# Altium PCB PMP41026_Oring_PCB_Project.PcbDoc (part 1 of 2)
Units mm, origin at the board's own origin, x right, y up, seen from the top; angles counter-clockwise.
Board outline 34.25 x 35.26 mm, 8 copper layers (Top Layer, Layer 2, Layer 3, Layer 4, Layer 5, Layer 6, Layer 7, Bottom Layer), stack 1.271 mm thick; 34 components, 15 nets, 290 pads, 1015 vias.
Unrouted connection lines stored in the file: 1.
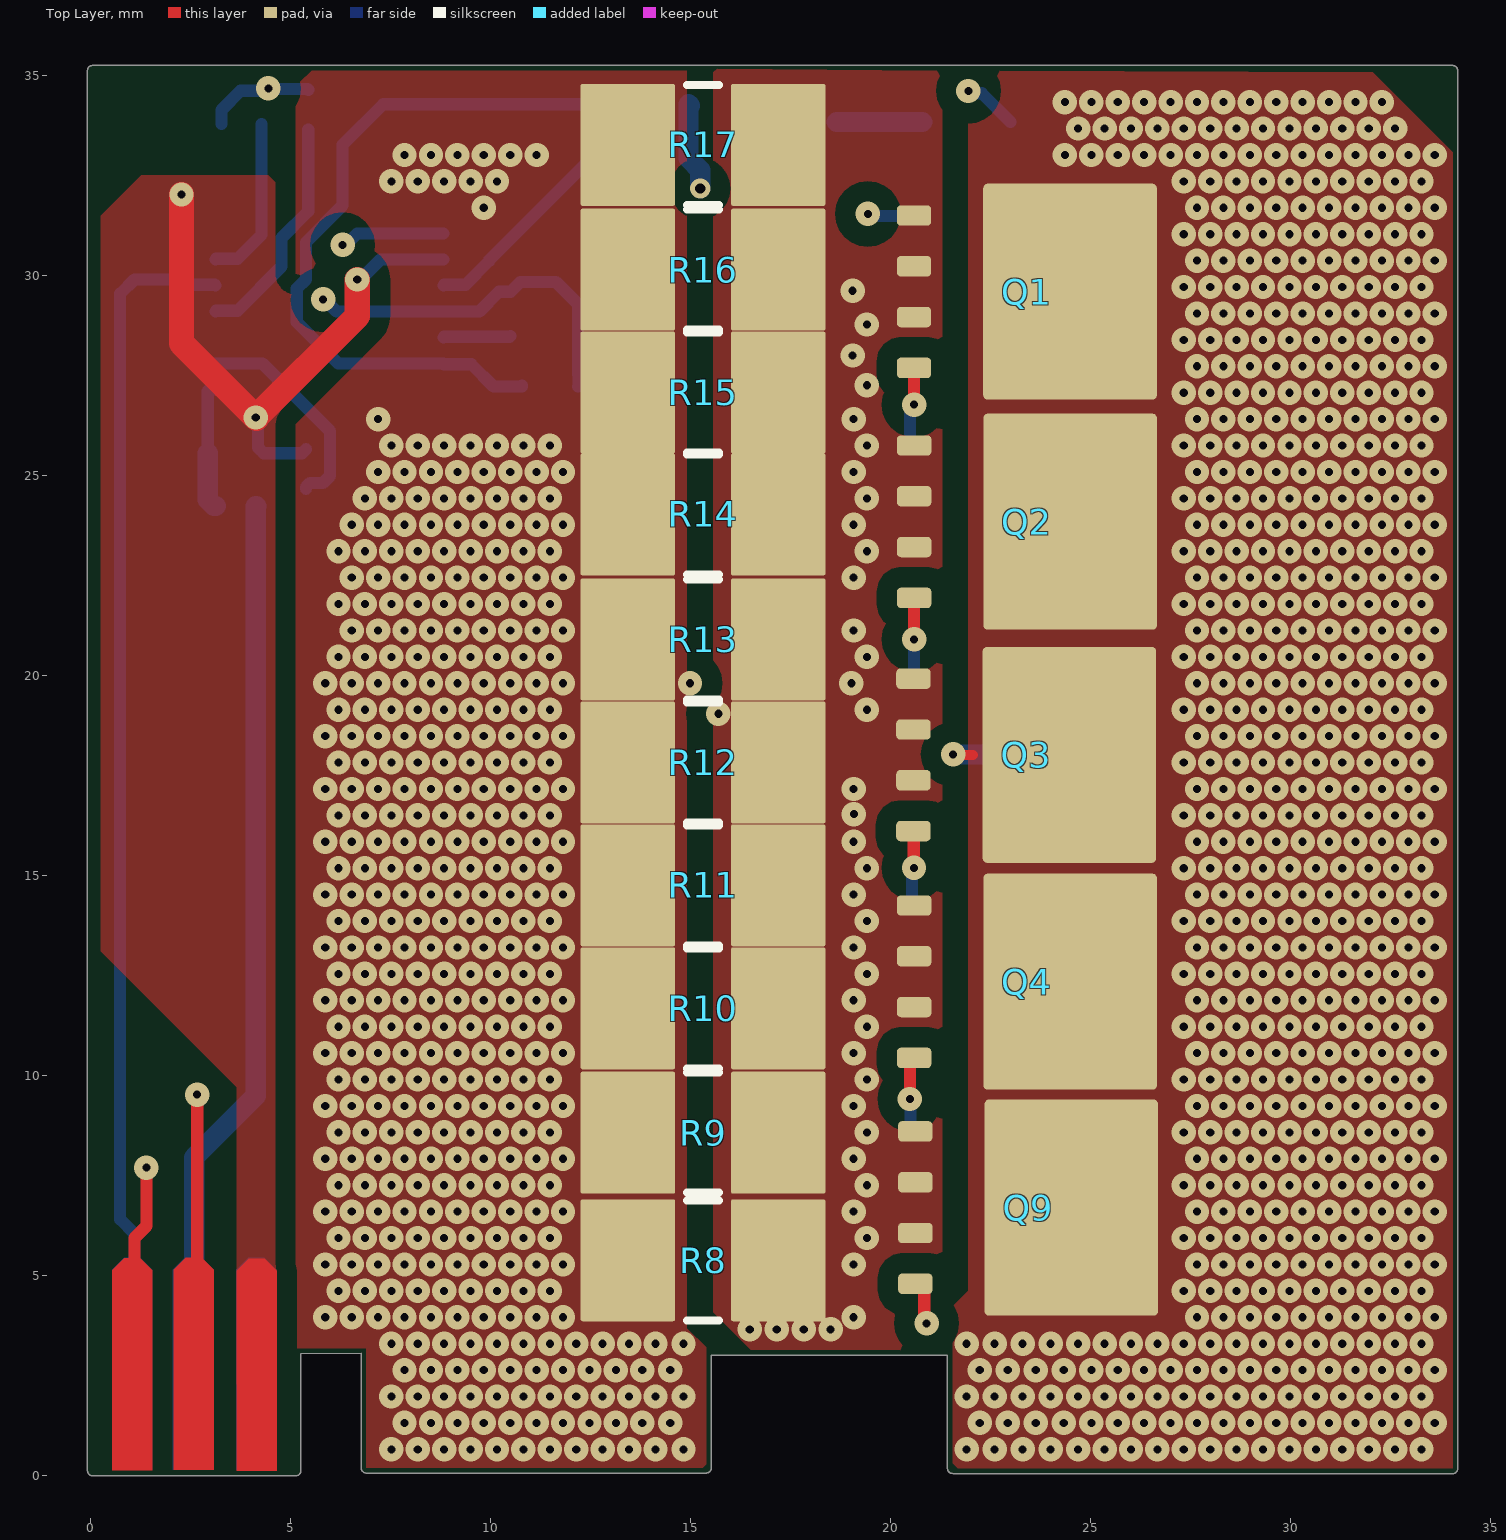
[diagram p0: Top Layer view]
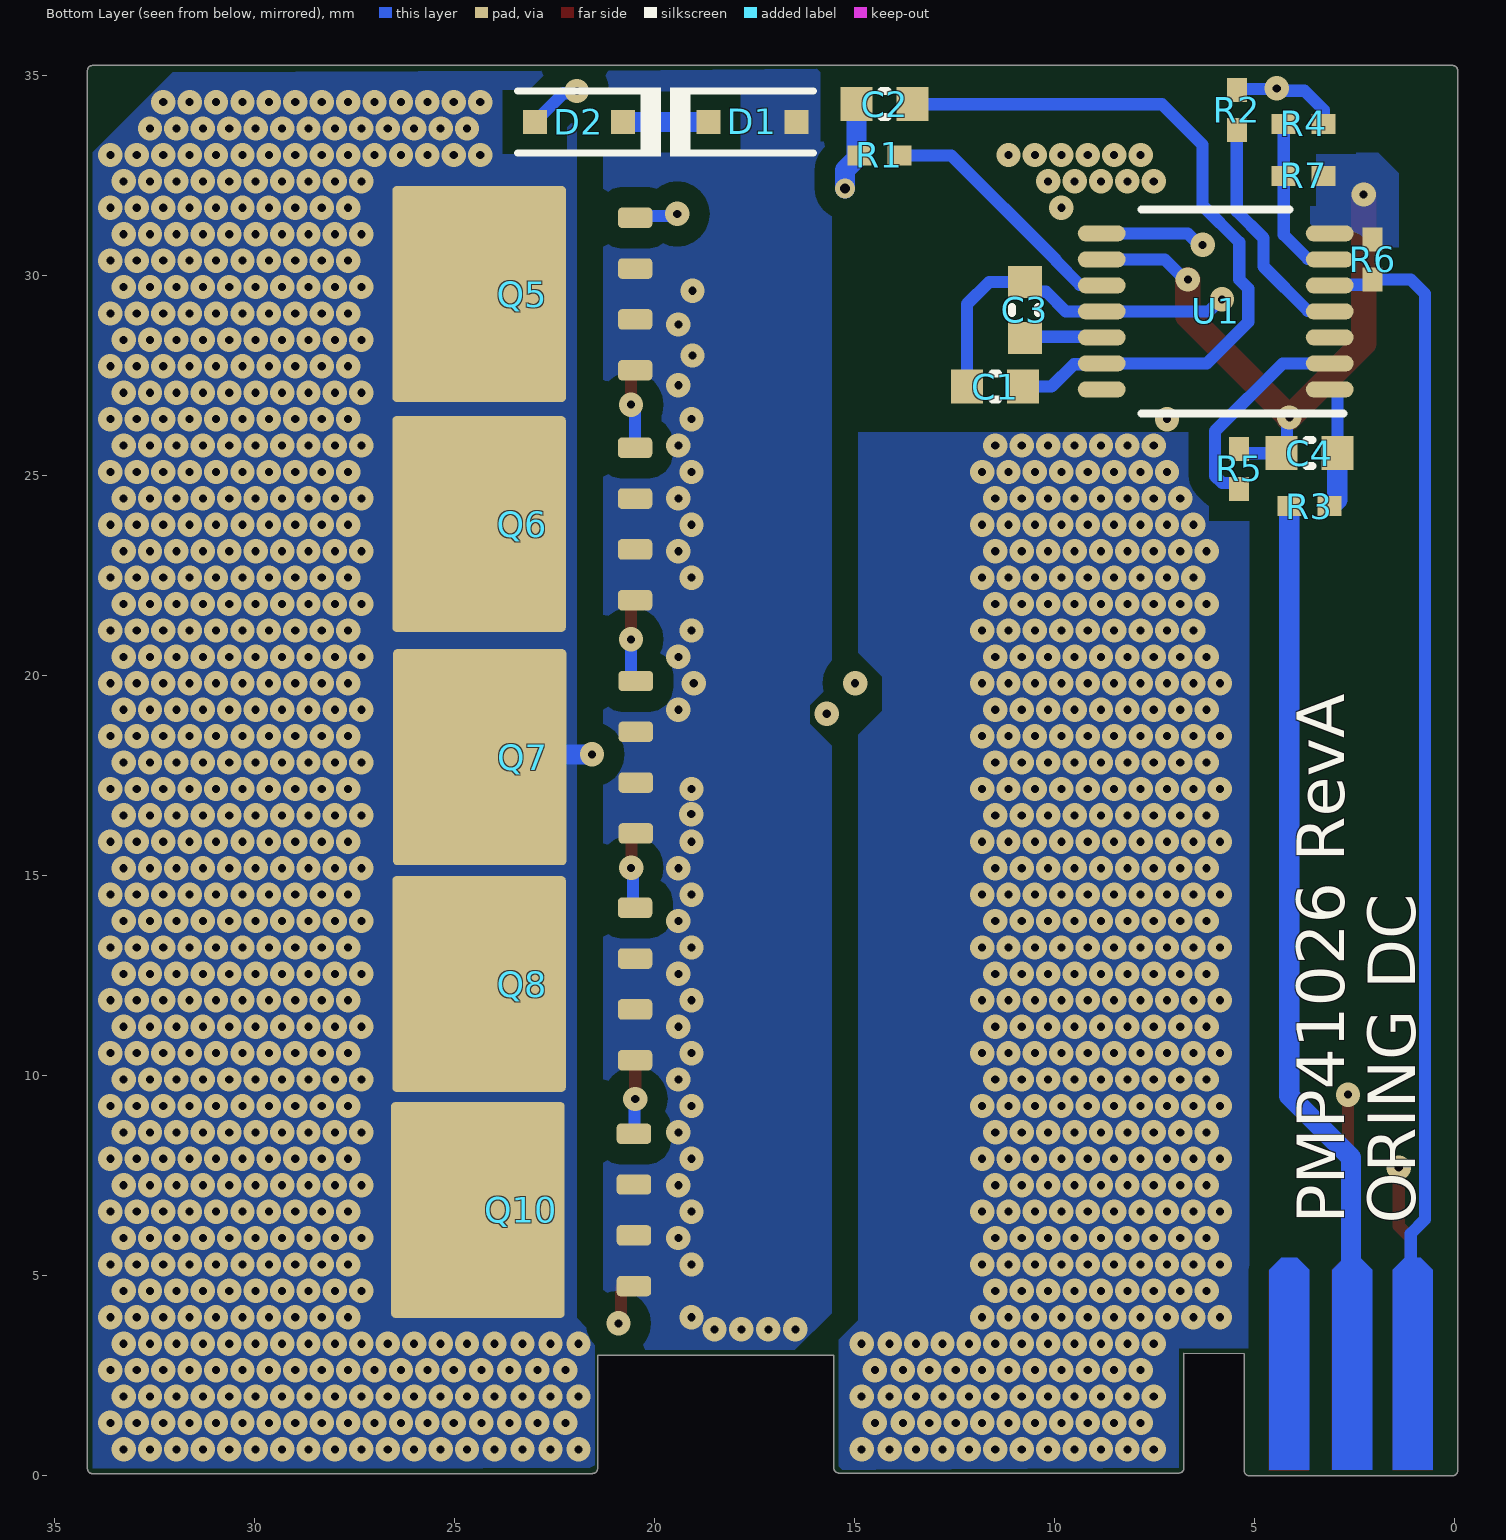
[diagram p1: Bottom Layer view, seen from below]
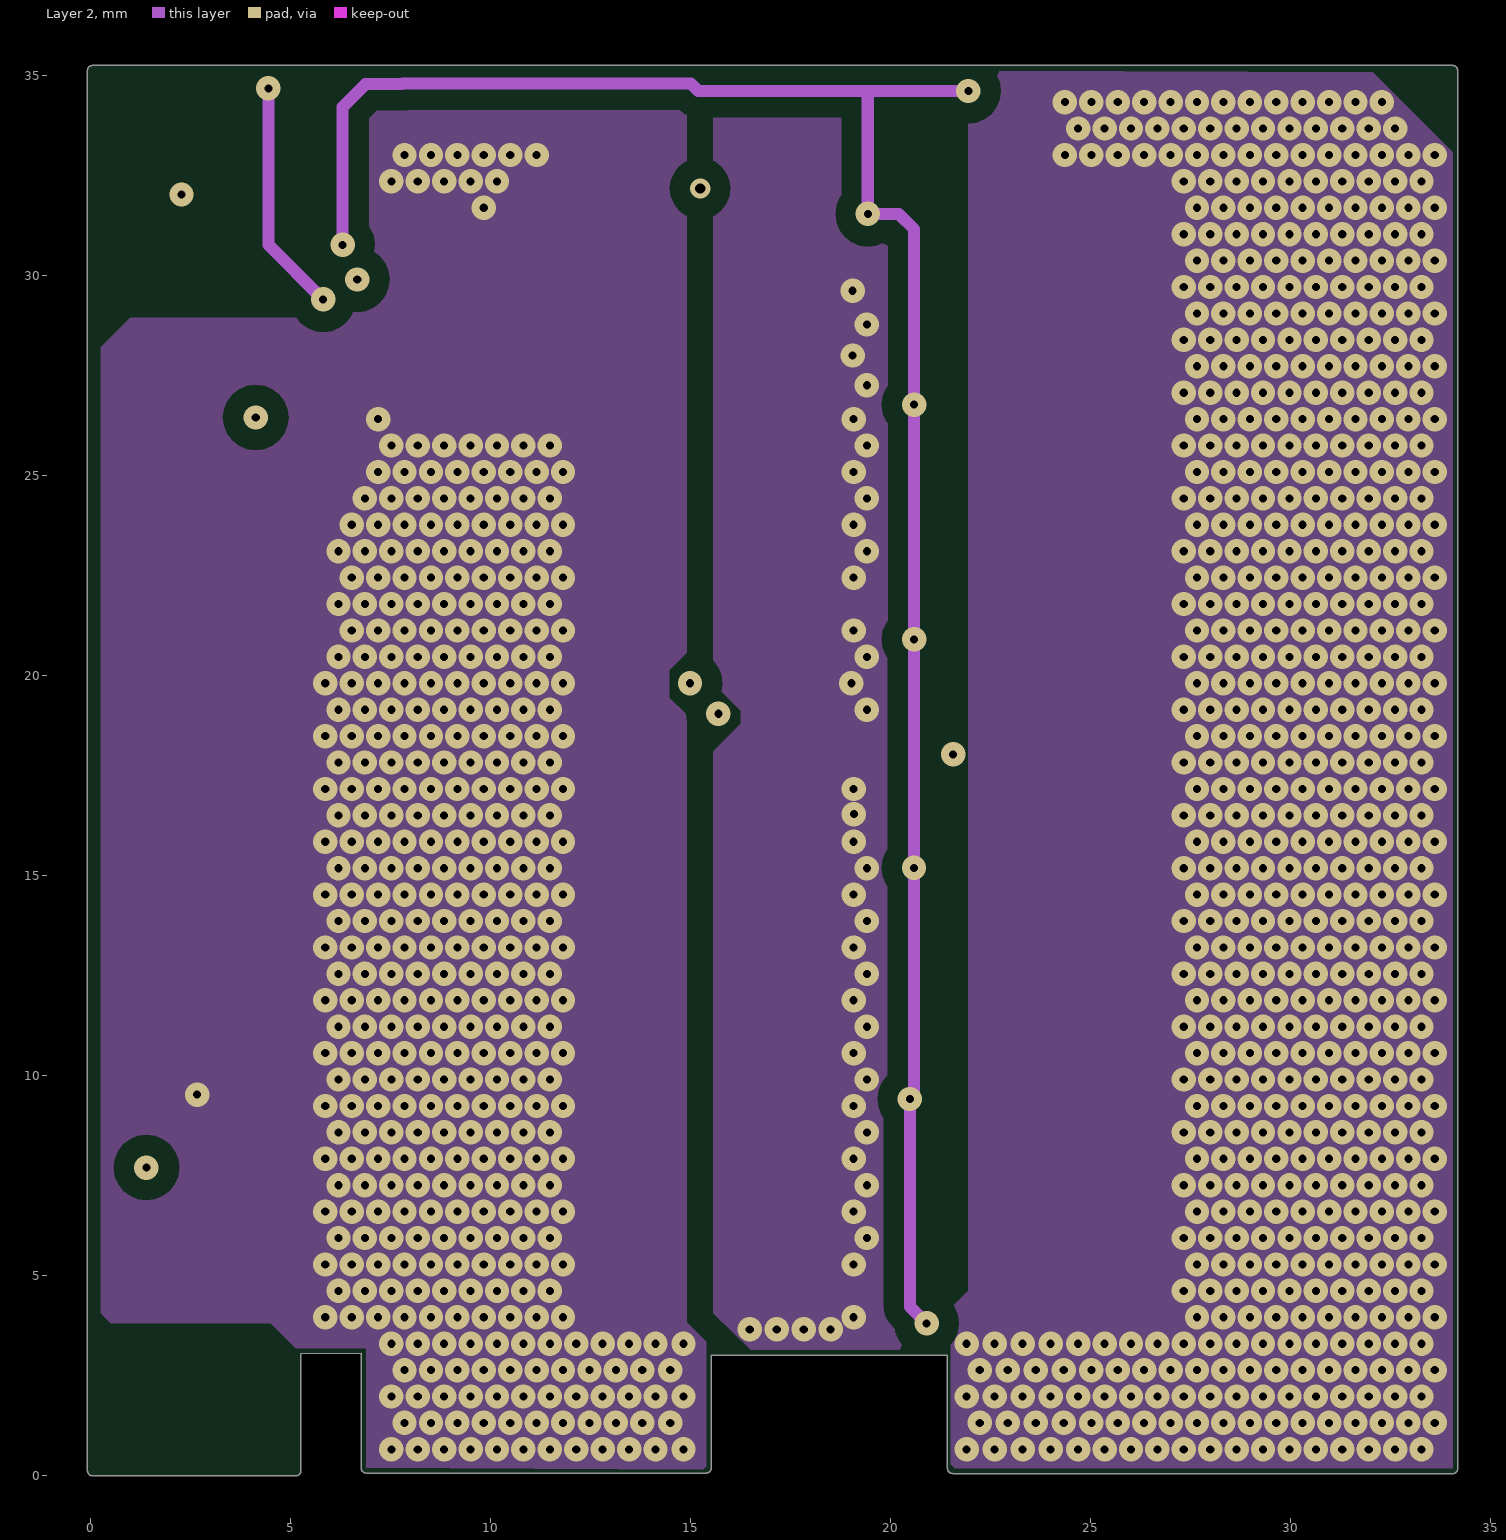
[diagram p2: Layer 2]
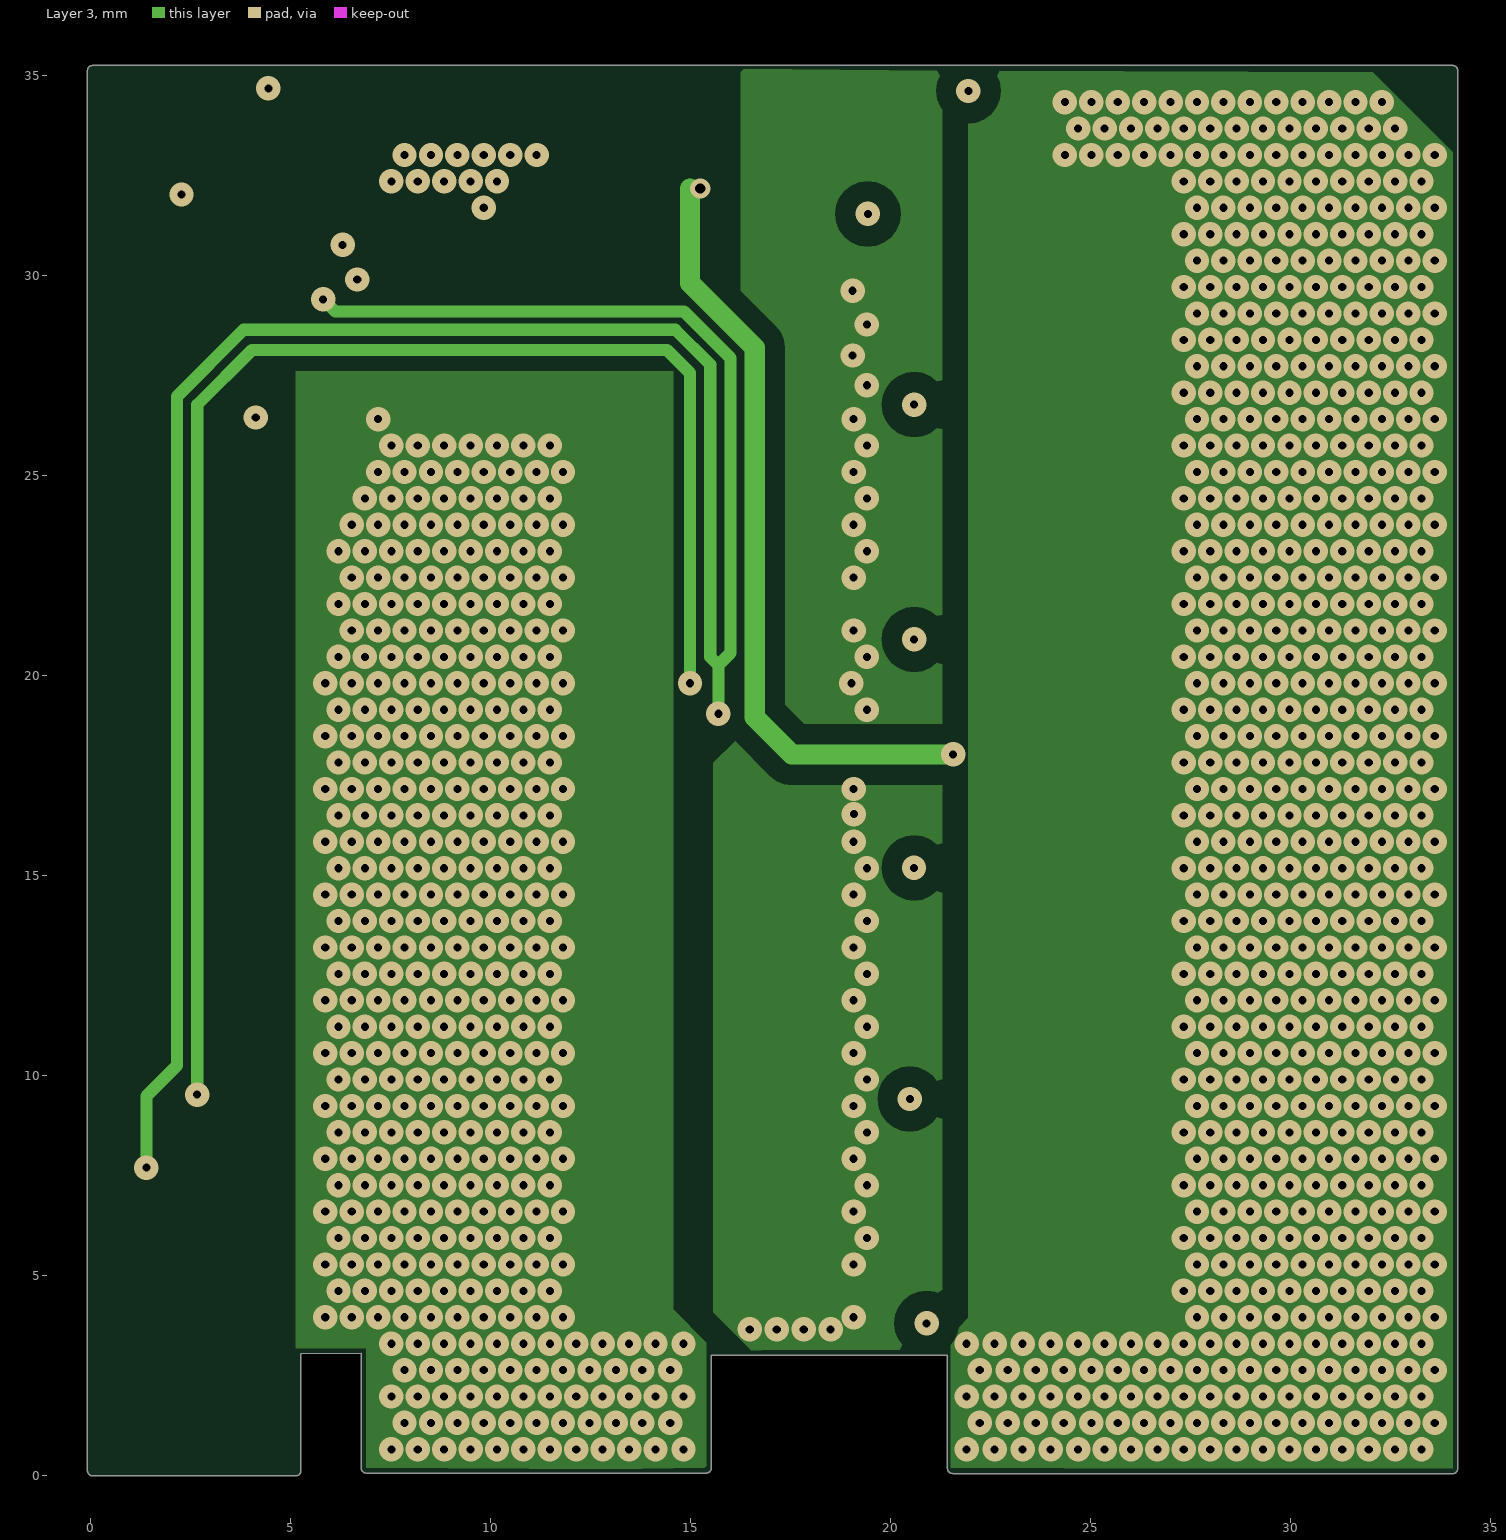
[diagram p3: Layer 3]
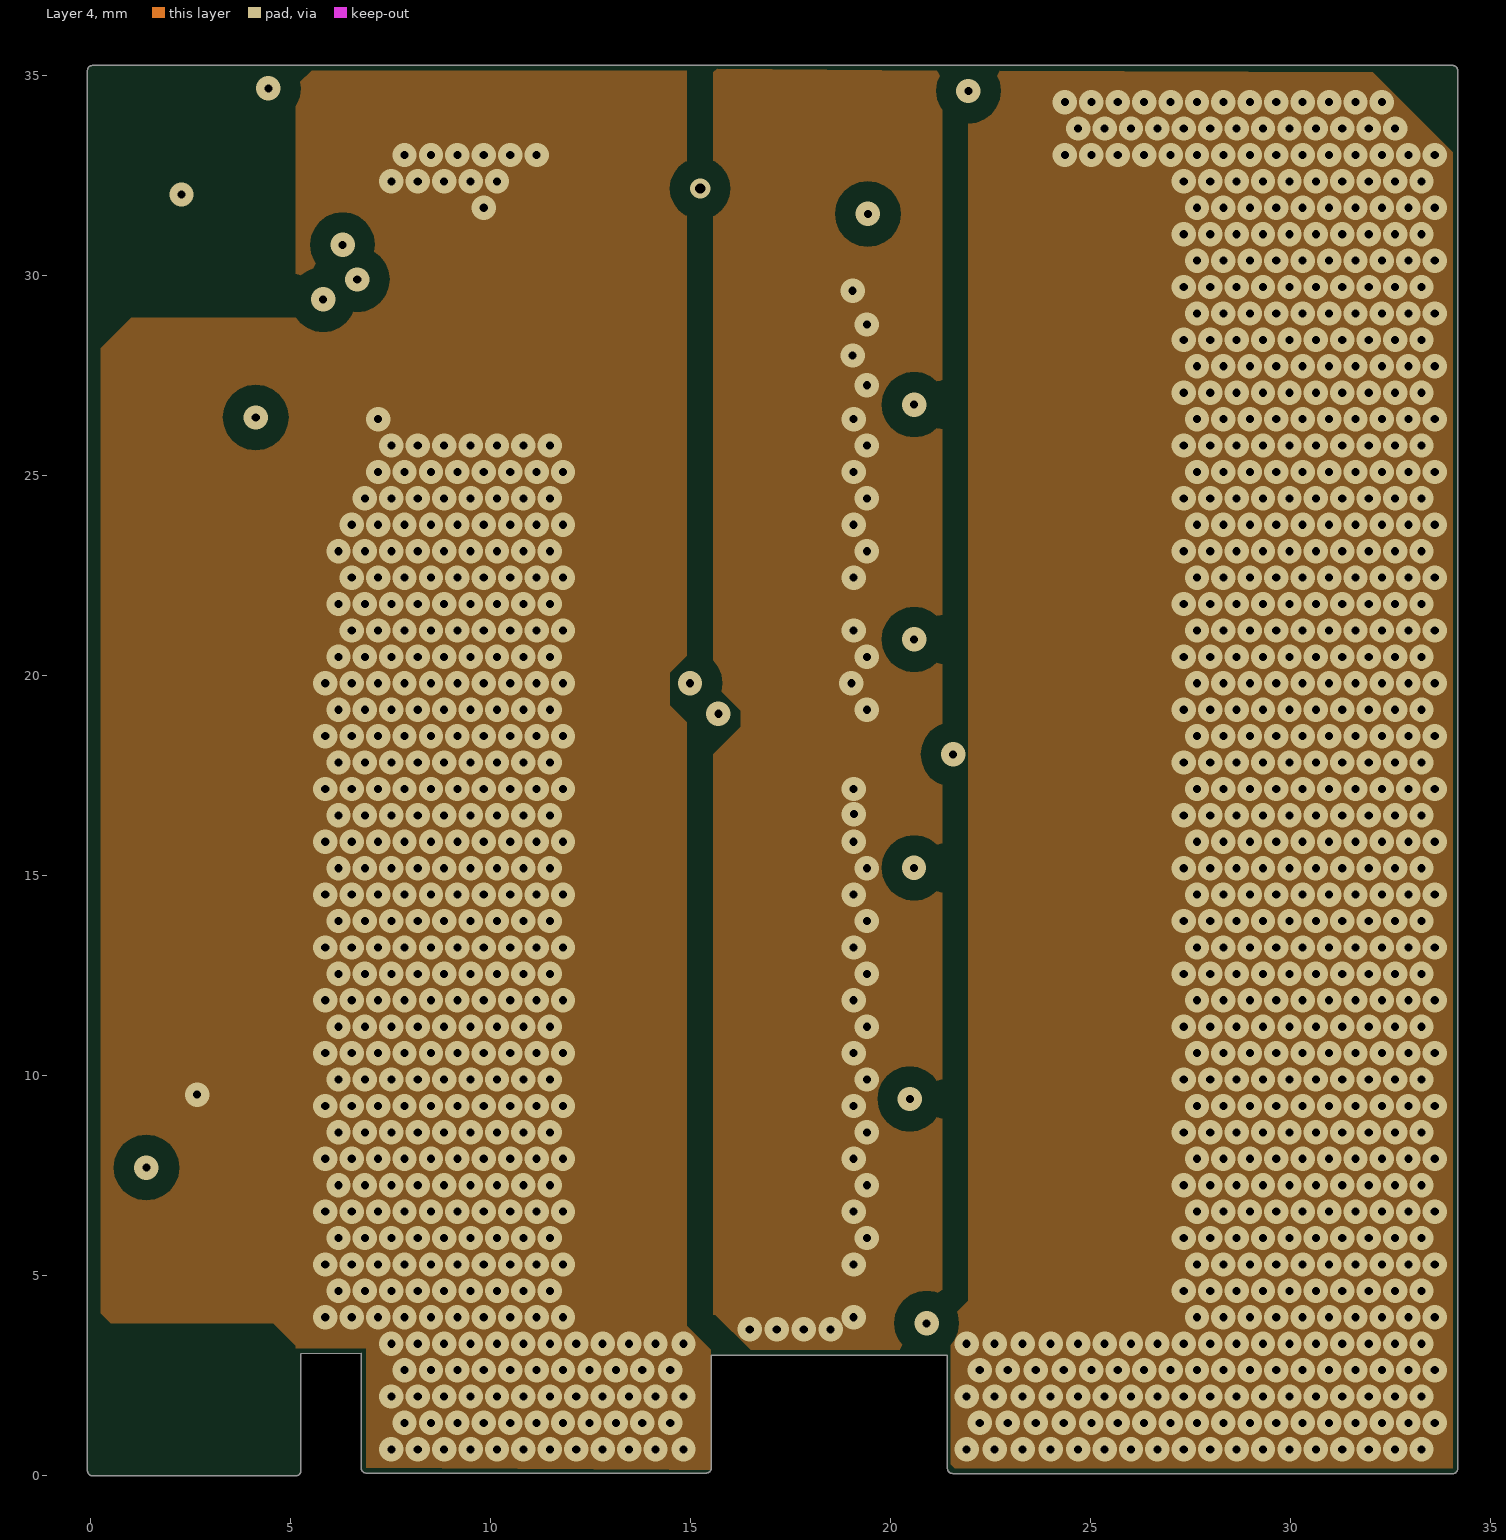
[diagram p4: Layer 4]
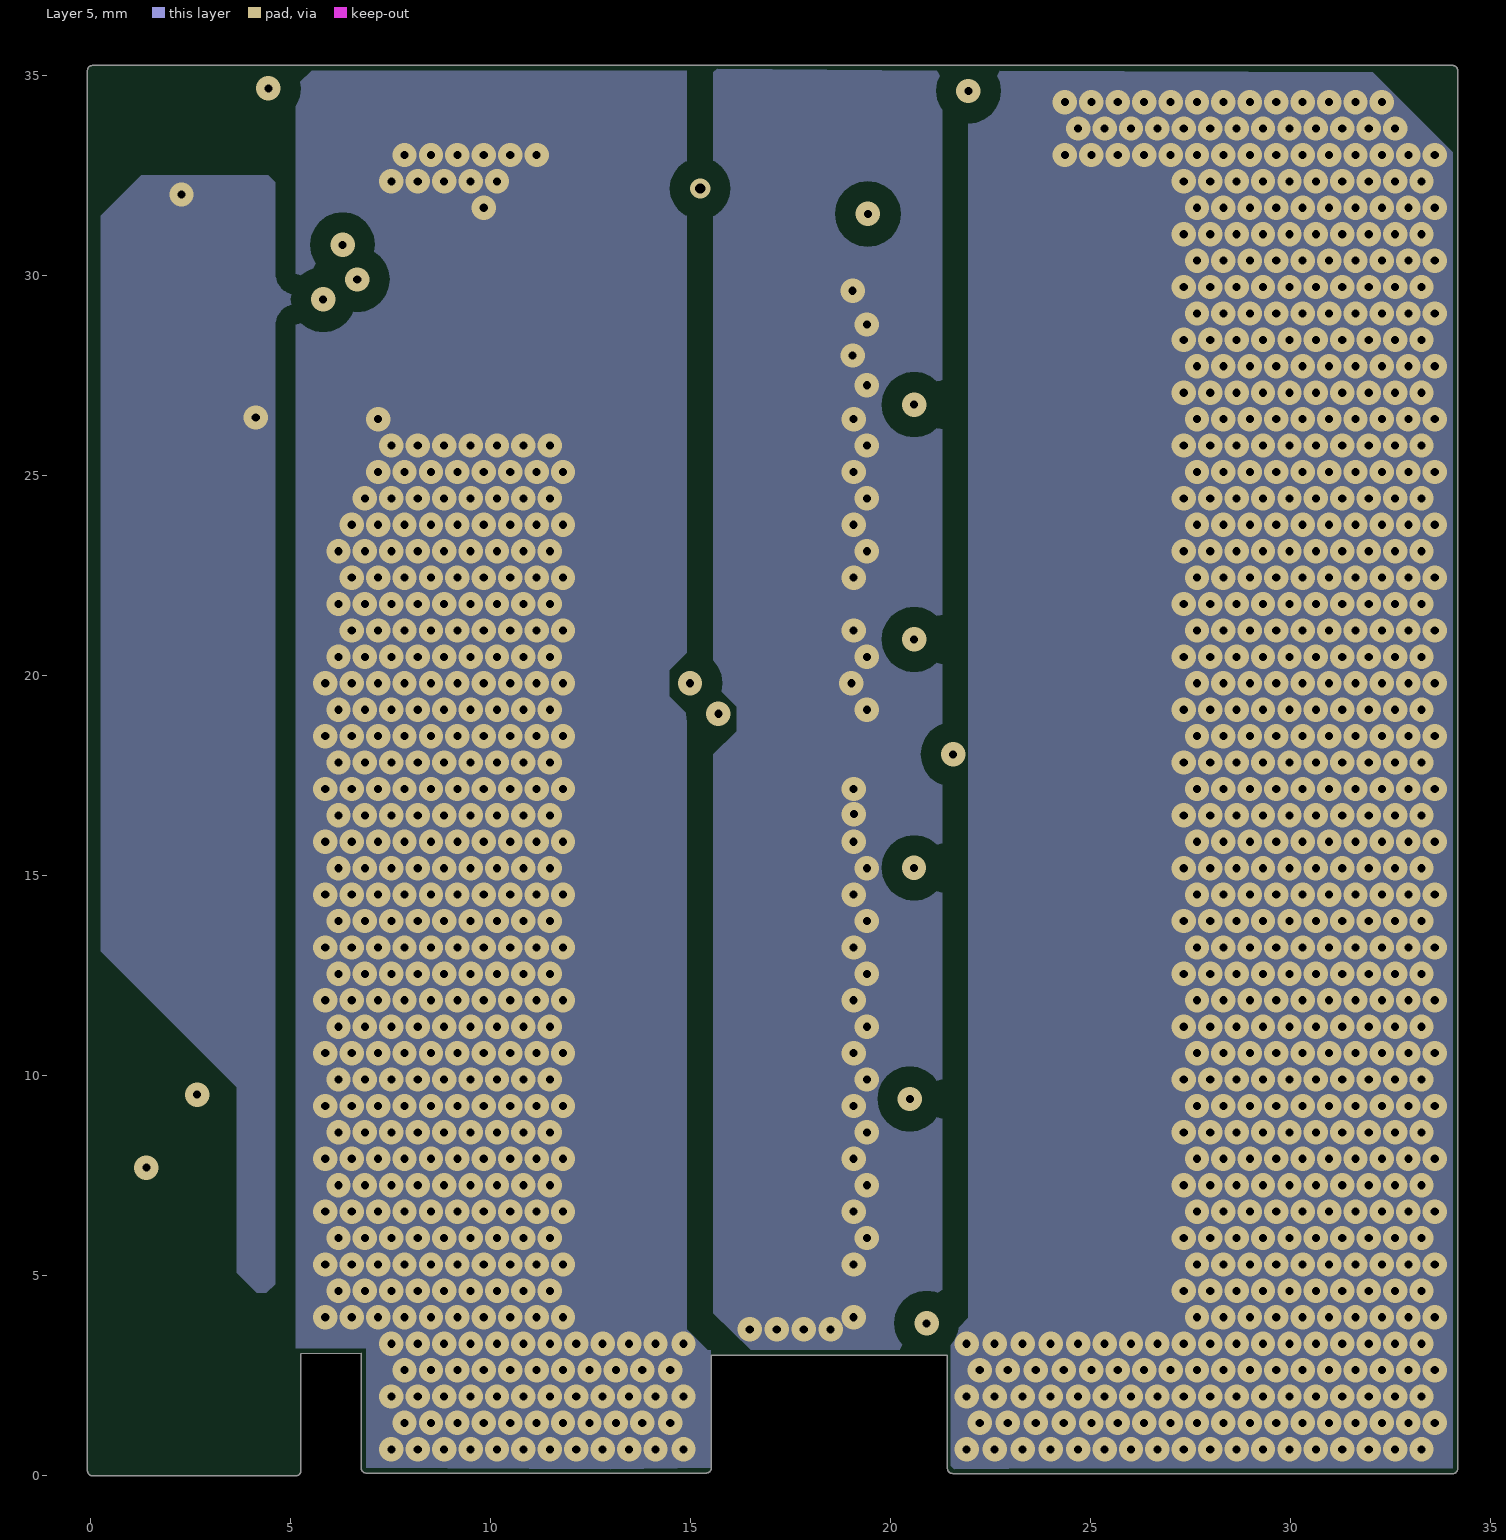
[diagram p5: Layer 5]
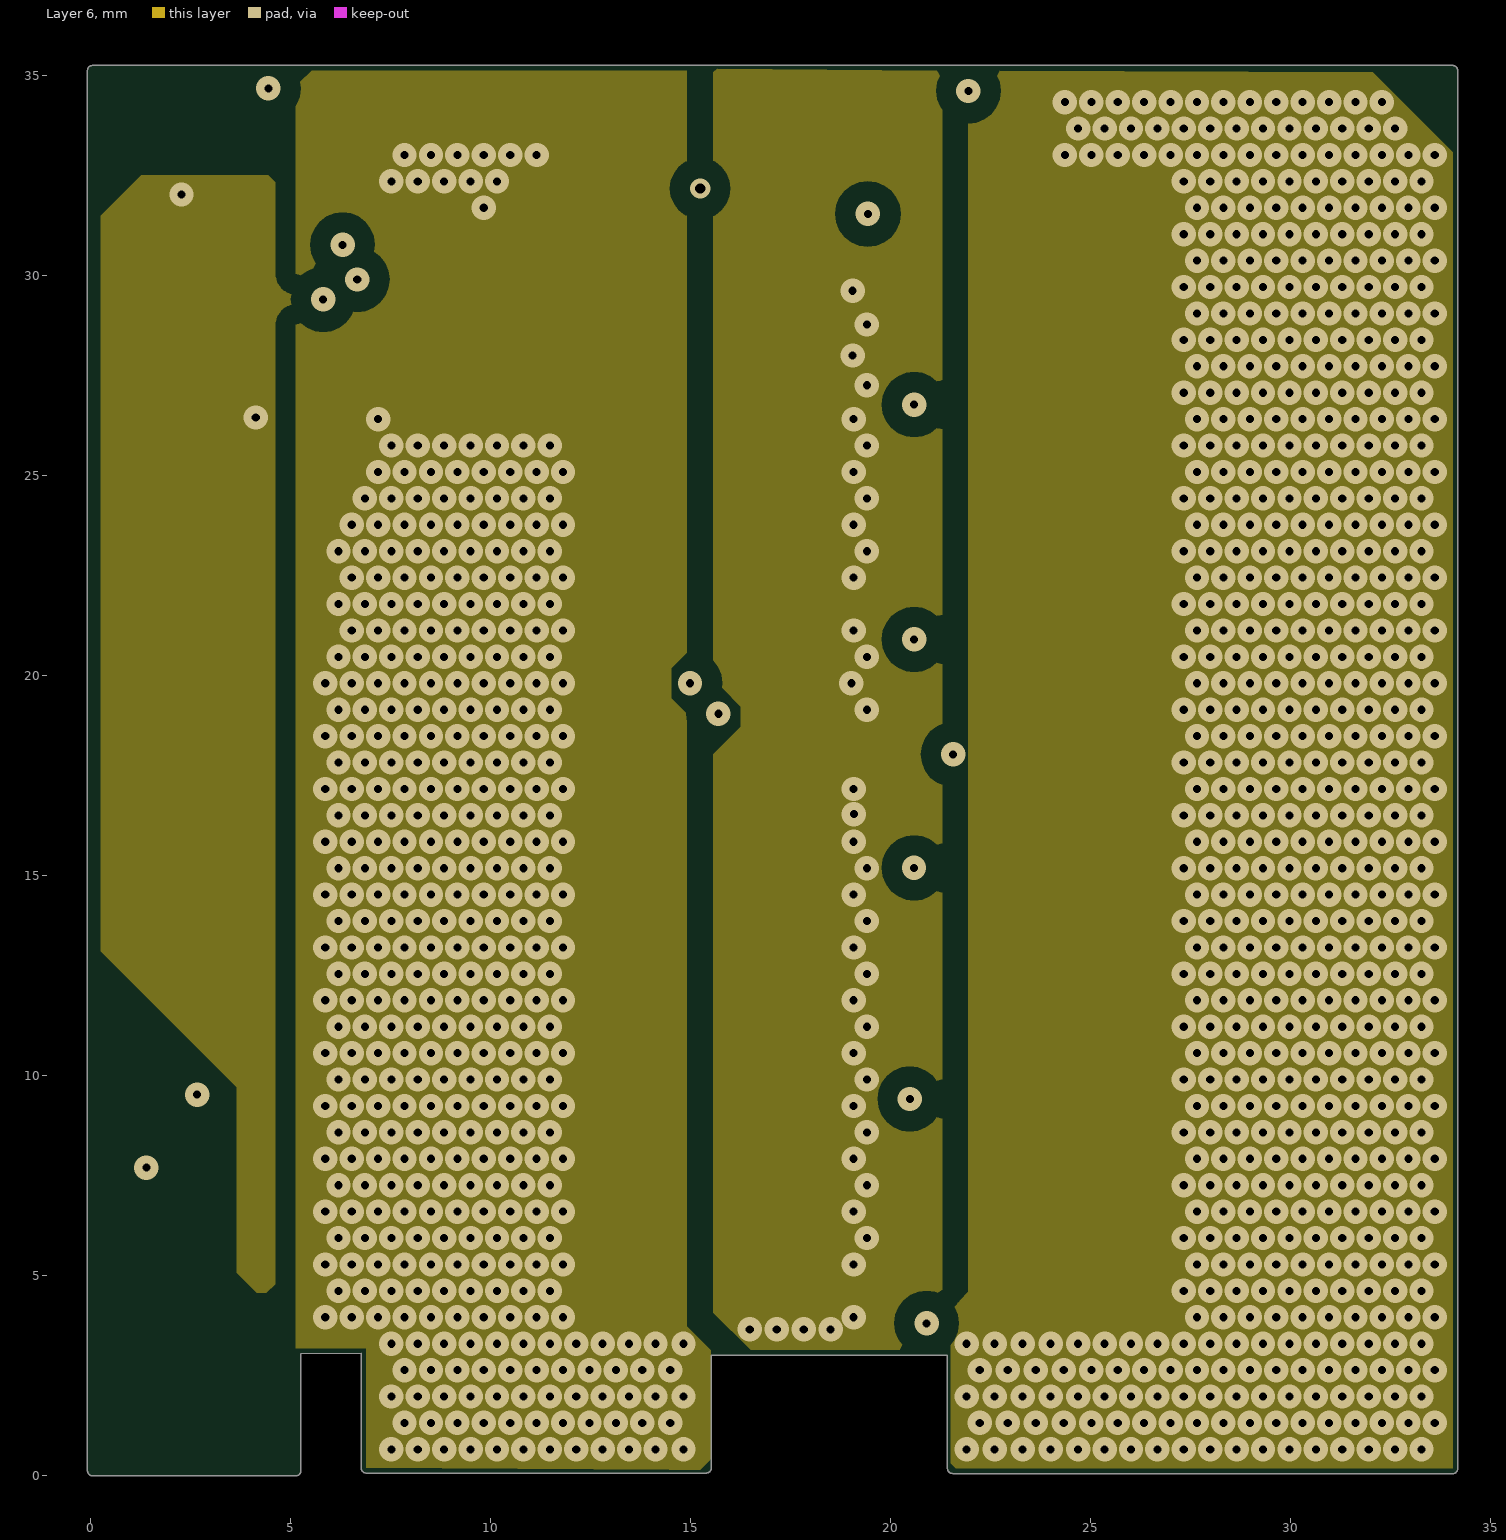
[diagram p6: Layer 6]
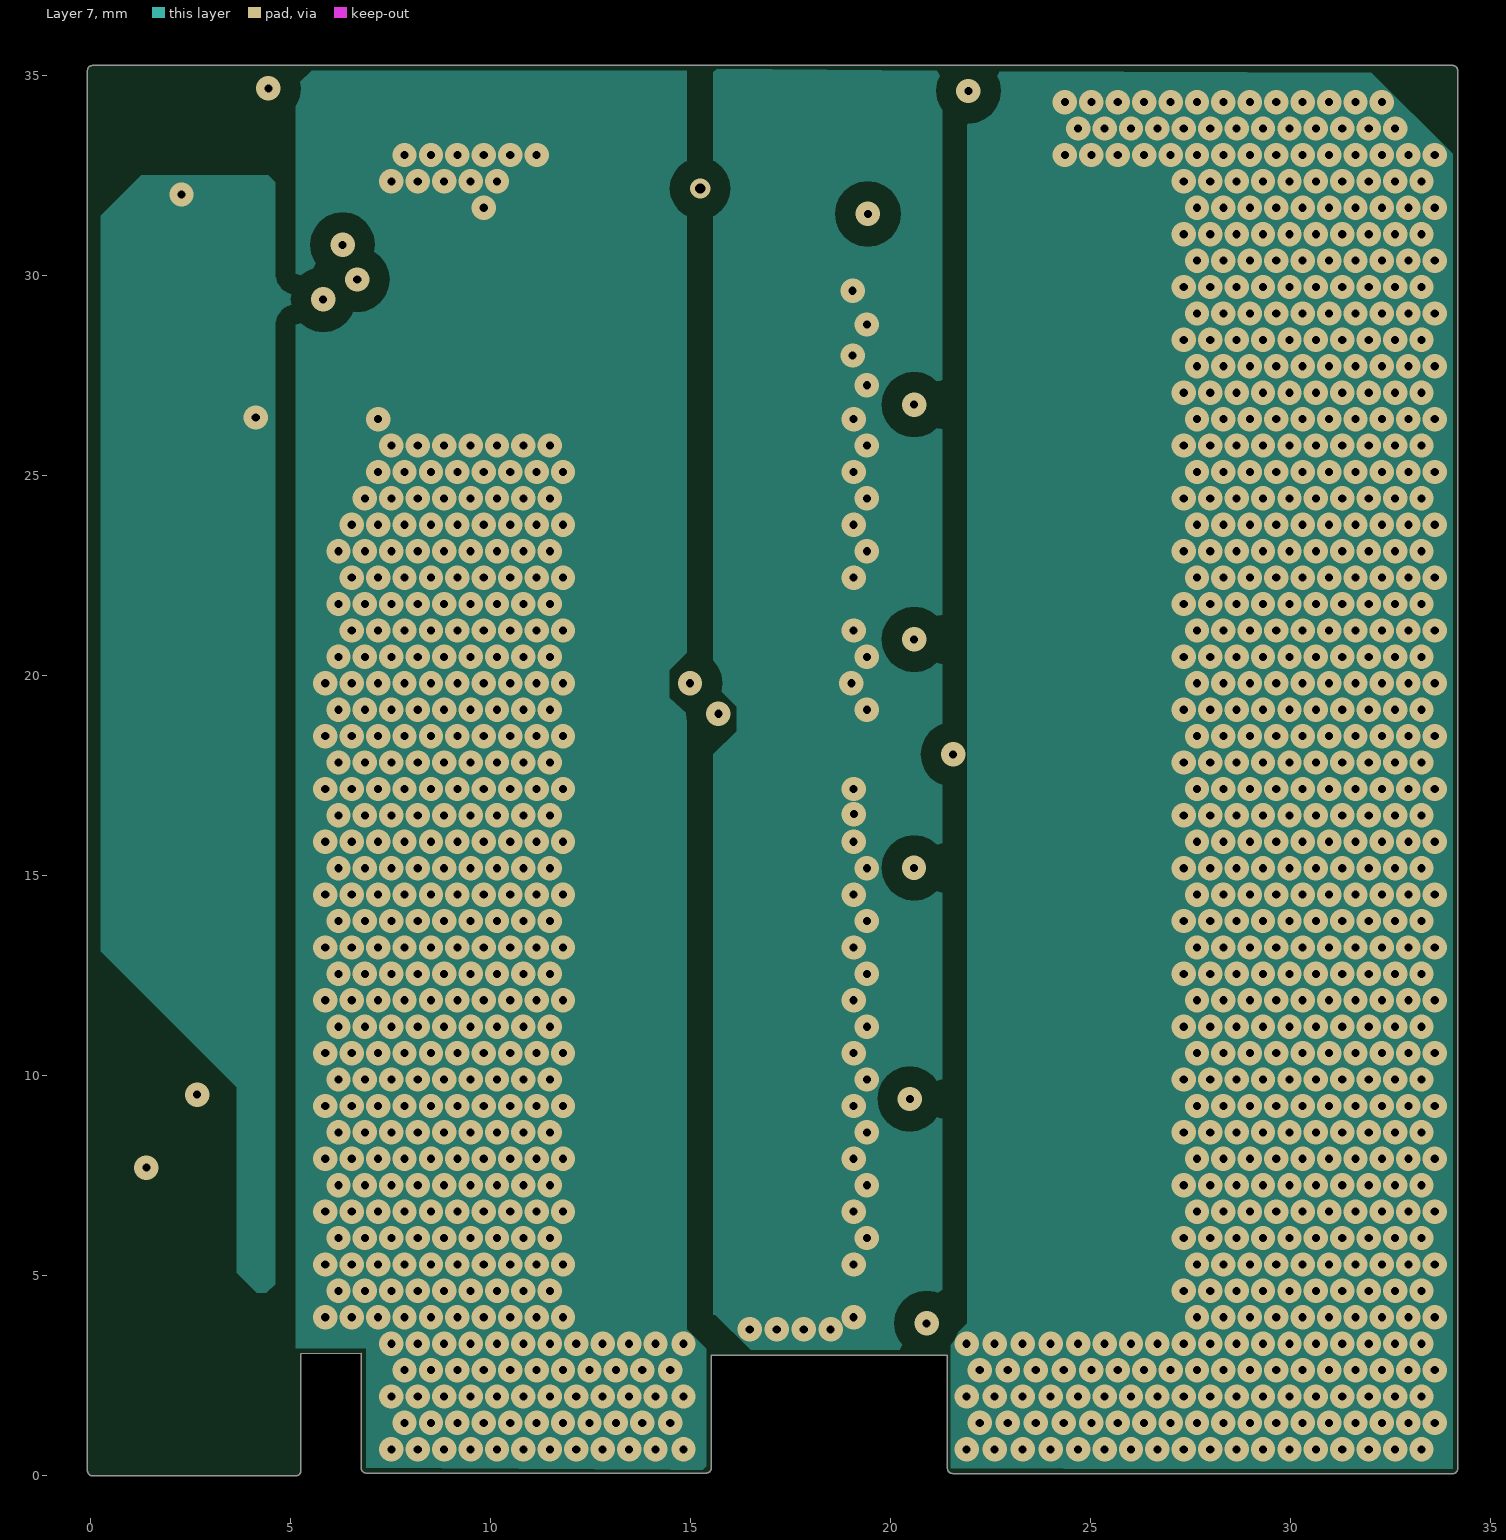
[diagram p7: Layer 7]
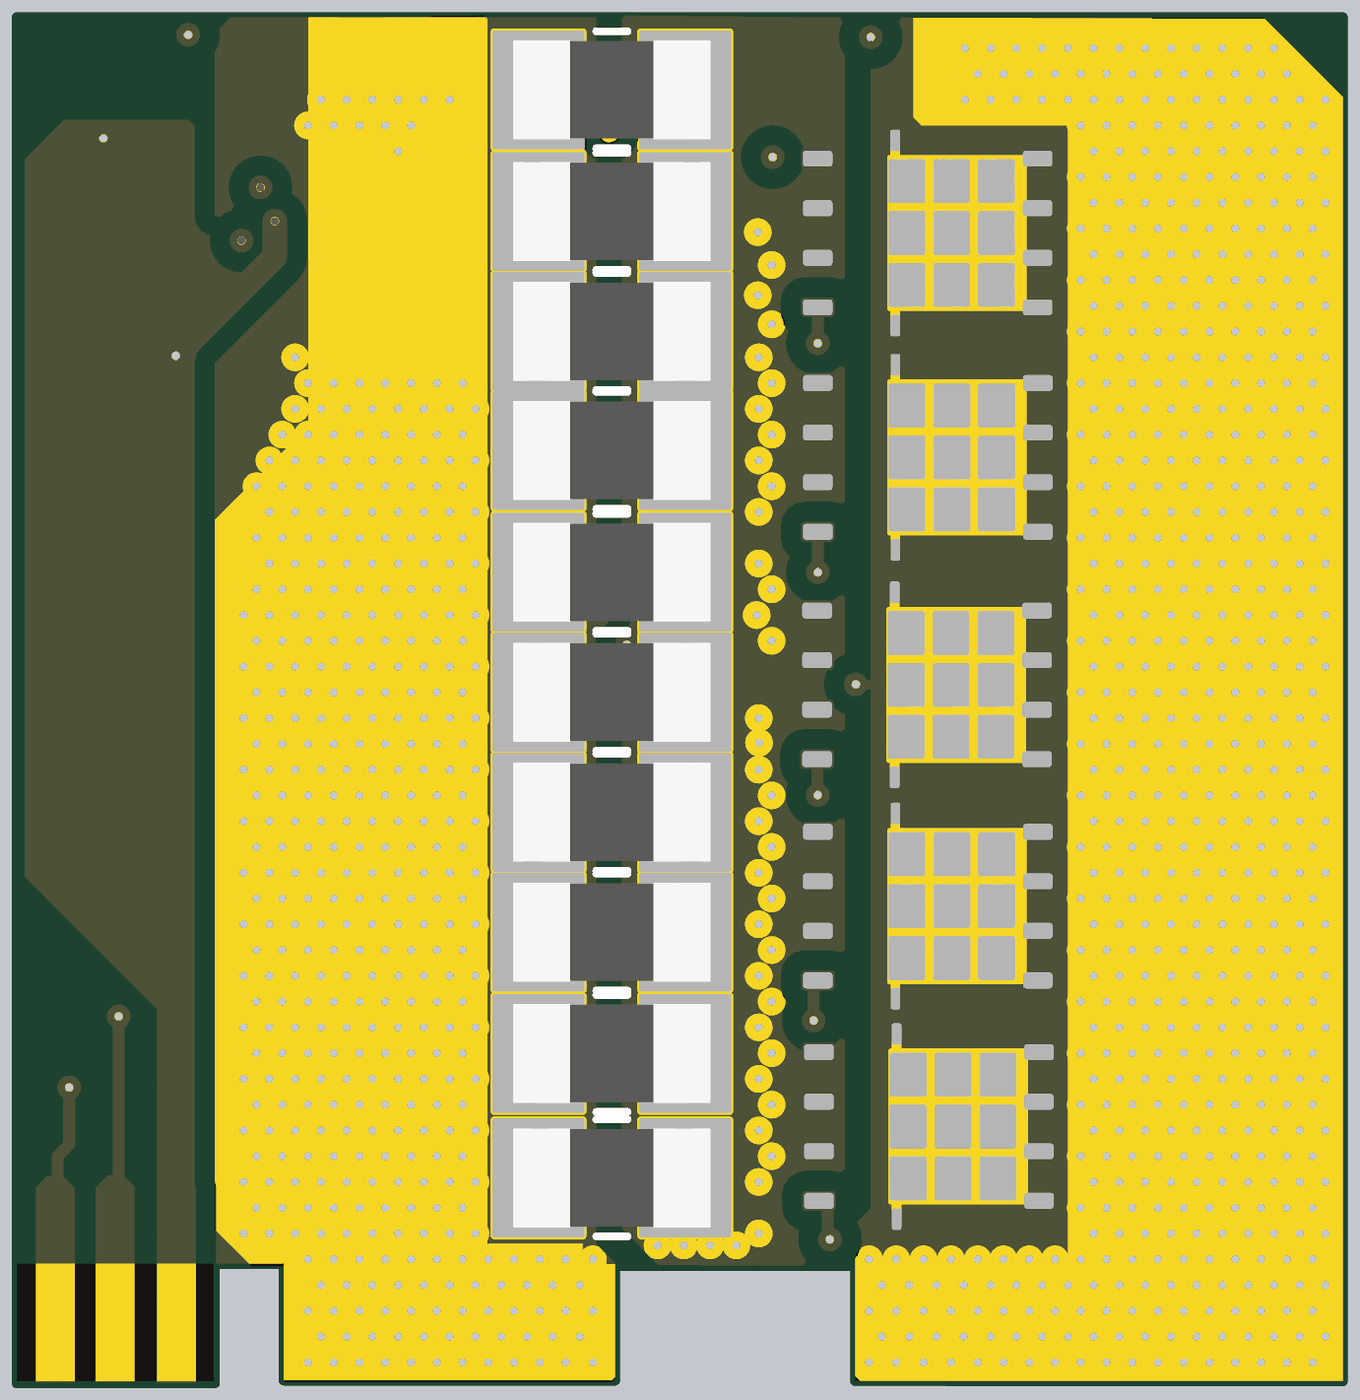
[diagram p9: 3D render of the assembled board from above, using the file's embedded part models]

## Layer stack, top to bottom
Top Solder: solder mask 0.0102, Solder Resist, Dk 3.5
Top Layer: signal copper 0.07
Dielectric 1: core 0.1016, Core-009, Dk 4.5
Layer 2: signal copper 0.07
Dielectric 3: core 0.1016, Core-009, Dk 4.5
Layer 3: signal copper 0.07
Dielectric 5: core 0.1016, Core-009, Dk 4.5
Layer 4: signal copper 0.07
Dielectric1: core 0.1016, Core-009, Dk 4.5
Layer 5: signal copper 0.07
Dielectric 6: core 0.1016, Core-009, Dk 4.5
Layer 6: signal copper 0.07
Dielectric 4: core 0.1016, Core-009, Dk 4.5
Layer 7: signal copper 0.07
Dielectric 2: core 0.1016, Core-009, Dk 4.5
Bottom Layer: signal copper 0.07
Bottom Solder: solder mask 0.0102, Solder Resist, Dk 3.5

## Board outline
0.049,0 5.131,0 ccw(c5.131,0.127) 5.258,0.127 ccw(c5.131,0.127) 5.256,0.152 ccw(c5.131,0.178) 5.258,0.178 5.258,3.054 6.764,3.06 6.764,0.195 ccw(c6.891,0.195) 6.891,0.068 15.391,0.068 ccw(c15.391,0.195) 15.519,0.195 ccw(c15.391,0.195) 15.519,0.198 ccw(c15.391,0.202) 15.519,0.202 15.519,3.009 21.422,3.009 21.422,0.184 ccw(c21.549,0.184) 21.549,0.057 34.049,0.05 ccw(c34.049,0.178) 34.049,0.05 ccw(c34.049,0.178) 34.177,0.178 34.177,35.13 ccw(c34.049,35.13) 34.049,35.257 0.049,35.257 ccw(c0.049,35.13) -0.078,35.13 -0.078,0.127 ccw(c0.049,0.127)

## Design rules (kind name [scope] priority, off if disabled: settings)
AcuteAngle [All] p1: minimum=4.50000000000000E+0001 checktracksonly=FALSE
AssemblyTestPointUsage [All] p1: valid=2
Clearance Clearance_2 [InNetClass('HV') vs Not InNetClass('HV')] p1: gap=1.524 ignorepadtopadclearanceinfootprint=TRUE except(0: Arc-Hole Track-Hole SMDPad-Hole THPad-Hole Via-Hole Fill-Hole Poly-Hole Region-Hole Text-Hole)
Clearance Clearance_1 [InNetClass('MV') vs Not InNetClass('MV')] p2: gap=1.016 ignorepadtopadclearanceinfootprint=TRUE
Clearance Clearance_Keepouts [((IsTrack Or IsArc) And Not InPoly) And IsFree and IsKeepOut vs ((IsTrack Or IsArc) And Not InPoly) And IsFree and IsKeepOut] p3: gap=0 ignorepadtopadclearanceinfootprint=FALSE
Clearance Clearance_BoardEdge_MountingHoles [OnCopper and InComponentClass('Mounting Holes') vs IsKeepOut] p4: gap=1.016 ignorepadtopadclearanceinfootprint=FALSE except(0: Arc-Hole Track-Hole SMDPad-Hole THPad-Hole Via-Hole Fill-Hole Poly-Hole Region-Hole Text-Hole)
Clearance Clearance_BoardEdge_Poly [OnCopper and InPoly vs IsKeepOut] p5: gap=0.635 ignorepadtopadclearanceinfootprint=FALSE except(0: Arc-Hole Track-Hole SMDPad-Hole THPad-Hole Via-Hole Fill-Hole Poly-Hole Region-Hole Text-Hole)
Clearance Clearance_BoardEdge [OnCopper and Not InComponentClass('Logo') and not InComponentClass('FiducialMark') and not InRegion(1000,500,4000,800) and Not IsKeepout vs IsKeepOut] p6: gap=1.905 ignorepadtopadclearanceinfootprint=FALSE except(0: Arc-Hole Track-Hole SMDPad-Hole THPad-Hole Via-Hole Fill-Hole Poly-Hole Region-Hole Text-Hole)
Clearance Clearance_Poly [InPolygon] p7: gap=0.508 ignorepadtopadclearanceinfootprint=FALSE except(0: Arc-Hole Track-Hole SMDPad-Hole THPad-Hole Via-Hole Fill-Hole Poly-Hole Region-Hole Text-Hole)
Clearance [All] p8: gap=0.2 ignorepadtopadclearanceinfootprint=FALSE except(0: Arc-SMDPad Arc-Hole Track-Hole SMDPad-Hole THPad-Hole Via-Hole Fill-Hole Poly-Hole Region-Hole Text-Hole)
ComponentClearance ComponentClearance_MountingHoles_FiducialMarks [InComponentClass('Mounting Holes') vs InComponentClass('FiducialMark')] p1: gap=0.508 collisioncheckmode=3 verticalgap=0.178 showdistances=FALSE
ComponentClearance ComponentClearance_Shunt [InComponentClass('Header') vs InComponentClass('Shunt')] p2: gap=0 collisioncheckmode=3 verticalgap=0 showdistances=FALSE
ComponentClearance ComponentClearance_Logo [InComponentClass('Logo')] p3: gap=0.127 collisioncheckmode=3 verticalgap=0.254 showdistances=FALSE
ComponentClearance ComponentClearance_ScrewToNut [(HasFootprint('KEYSTONE_4824')) vs (HasFootprint('Keystone_1903C'))] p4: gap=0 collisioncheckmode=3 verticalgap=0 showdistances=FALSE
ComponentClearance ComponentClearance_MountingHoles [InComponentClass('Mounting Holes')] p5: gap=0.508 collisioncheckmode=3 verticalgap=0.178 showdistances=FALSE
ComponentClearance ComponentClearance_SmallPassives [HasFootprint('0201*') or HasFootprint('0402*') or HasFootprint('0508') or HasFootprint('0603*') or HasFootprint('0612') or HasFootprint('0805*') or HasFootprint('0815*') or HasFootprint('0830*') or HasFootprint('1206*') or HasFootprint('1210*') or HasFootprint('1808*') or HasFootprint('1812*') or HasFootprint('1825*') or HasFootprint('2010*') or HasFootprint('2220*') or HasFootprint('2225*') or HasFootprint('2512*') or HasFootprint('2728*') or HasFootprint('3518*') vs HasFootprint('0201*') or HasFootprint('0402*') or HasFootprint('0508') or HasFootprint('0603*') or HasFootprint('0612') or HasFootprint('0805*') or HasFootprint('0815*') or HasFootprint('0830*') or HasFootprint('1206*') or HasFootprint('1210*') or HasFootprint('1808*') or HasFootprint('1812*') or HasFootprint('1825*') or HasFootprint('2010*') or HasFootprint('2220*') or HasFootprint('2225*') or HasFootprint('2512*') or HasFootprint('2728*') or HasFootprint('3518*')] p6: gap=0.508 collisioncheckmode=3 verticalgap=0.508 showdistances=FALSE
ComponentClearance ComponentClearance_THtoSMT [IsThruComponent vs IsSMTComponent] p7: gap=0.254 collisioncheckmode=3 verticalgap=0.178 showdistances=FALSE
ComponentClearance ComponentClearance_THtoTH [IsThruComponent vs IsThruComponent] p8: gap=0.254 collisioncheckmode=3 verticalgap=0.178 showdistances=FALSE
ComponentClearance [All] p9: gap=0.254 collisioncheckmode=3 verticalgap=0.178 showdistances=FALSE
DiffPairsRouting [All] p1: maxlimit=2.54 minlimit=0.254 mostfreqgap=0.254 toplayer_minwidth=0.381 toplayer_maxwidth=0.381 toplayer_prefwidth=0.381 midlayer1_minwidth=0.381 midlayer1_maxwidth=0.381 midlayer1_prefwidth=0.381 midlayer2_minwidth=0.381 midlayer2_maxwidth=0.381 midlayer2_prefwidth=0.381 midlayer3_minwidth=0.381 midlayer3_maxwidth=0.381 midlayer3_prefwidth=0.381 midlayer4_minwidth=0.381 midlayer4_maxwidth=0.381 midlayer4_prefwidth=0.381 midlayer5_minwidth=0.381 midlayer5_maxwidth=0.381 midlayer5_prefwidth=0.381 midlayer6_minwidth=0.381 midlayer6_maxwidth=0.381 midlayer6_prefwidth=0.381 bottomlayer_minwidth=0.381 bottomlayer_maxwidth=0.381 bottomlayer_prefwidth=0.381 maxuncoupledlength=25.4
FabricationTestPointUsage TestPointUsage [All] p1: valid=2 allowmultiple=FALSE
FabricationTestpoint Testpoint [All] p1: side=3 testpointundercomponent=TRUE minsize=1.016 maxsize=2.54 preferedsize=1.524 minholesize=0 maxholesize=1.016 preferedholesize=0.813 testpointgrid=0.025 allowsidetop=TRUE allowsidebottom=TRUE usegrid=TRUE gridtolerance=0
FanoutControl Fanout_LCC [IsLCC] p1: bgadir=Out bgaviamode=Centered fanoutstyle=Auto fanoutdirection=Alternating viagrid=0.025 // Fanout_LCC (Default Rule)
FanoutControl Fanout_BGA [IsBGA] p2: bgadir=Out bgaviamode=Centered fanoutstyle=Auto fanoutdirection=Alternating viagrid=0.025 // Fanout_BGA (Default Rule)
FanoutControl Fanout_Default [All] p4: bgadir=Out bgaviamode=Centered fanoutstyle=Auto fanoutdirection=Alternating viagrid=0.025 // Fanout_Default (Default Rule)
FanoutControl Fanout_Small [(CompPinCount < 5)] p5: bgadir=Out bgaviamode=Centered fanoutstyle=Auto fanoutdirection=OutThenIn viagrid=0.025 // Fanout_Small (Default Rule)
Height [All] p1: minheight=0 maxheight=76.2 prefheight=12.7
HoleSize [All] p1: absolutevalues=TRUE maxlimit=12.725 minlimit=0.178 maxpercent=80.000 minpercent=20.000
MinimumAnnularRing MinimumAnnularRing_ThermalPadVias [IsVia and InAnyComponent] p1: minimumring=0.15
MinimumAnnularRing [All] p2: minimumring=0.127
MinimumSolderMaskSliver MinimumSolderMaskSliver_Logo [InComponentClass('Logo') vs InComponentClass('Logo')] p1: minsoldermaskwidth=0.018
MinimumSolderMaskSliver [All] p2: minsoldermaskwidth=0.025
PlaneConnect [All] p1: planeconnectstyle=Direct reliefexpansion=0.254 reliefentries=4 reliefconductorwidth=0.254 reliefairgap=0.254
PolygonConnect PolygonConnect_16 [All vs IsNamedPolygon('C106_2') Or  IsNamedPolygon('Vout') Or  IsNamedPolygon('IN+') Or  IsNamedPolygon('Q203_5') Or  IsNamedPolygon('IN+') Or  IsNamedPolygon('Q201_5') Or  IsNamedPolygon('C108_2') Or  IsNamedPolygon('SGND') Or  IsNamedPolygon('IN+') Or  IsNamedPolygon('SGND') Or  IsNamedPolygon('Q203_5') Or  IsNamedPolygon('IN+') Or  IsNamedPolygon('SGND') Or  IsNamedPolygon('GND') Or  IsNamedPolygon('C113_2') Or  IsNamedPolygon('C107_2') Or  IsNamedPolygon('C107_2') Or  IsNamedPolygon('Vout') Or  IsNamedPolygon('SIGNAL_LAYER_1_GND_P074') Or  IsNamedPolygon('HV') Or  IsNamedPolygon('C108_2') Or  IsNamedPolygon('C103_2') Or  IsNamedPolygon('Q201_5') Or  IsNamedPolygon('Vout') Or  IsNamedPolygon('C109_2') Or  IsNamedPolygon('Q201_5') Or  IsNamedPolygon('GND') Or  IsNamedPolygon('C107_2') Or  IsNamedPolygon('C102_1') Or  IsNamedPolygon('GND') Or  IsNamedPolygon('SGND') Or  IsNamedPolygon('HS') Or  IsNamedPolygon('Q203_5') Or  IsNamedPolygon('Q201_5') Or  IsNamedPolygon('Q203_5')] p1: connectstyle=Direct reliefconductorwidth=0.254 reliefentries=4 polygonreliefangle="90 Angle" airgapwidth=0.254
PolygonConnect PolygonConnect_15 [All vs IsNamedPolygon('C109_2') Or  IsNamedPolygon('C107_2') Or  IsNamedPolygon('HV') Or  IsNamedPolygon('Q203_5') Or  IsNamedPolygon('C107_2') Or  IsNamedPolygon('HS') Or  IsNamedPolygon('Q201_5') Or  IsNamedPolygon('Q203_5') Or  IsNamedPolygon('C106_2') Or  IsNamedPolygon('C108_2') Or  IsNamedPolygon('Vout') Or  IsNamedPolygon('Q203_5') Or  IsNamedPolygon('C108_2') Or  IsNamedPolygon('C113_2') Or  IsNamedPolygon('Q203_5') Or  IsNamedPolygon('Q201_5') Or  IsNamedPolygon('C107_2') Or  IsNamedPolygon('C102_1') Or  IsNamedPolygon('SGND') Or  IsNamedPolygon('GND') Or  IsNamedPolygon('SGND') Or  IsNamedPolygon('GND') Or  IsNamedPolygon('IN+') Or  IsNamedPolygon('IN+') Or  IsNamedPolygon('Q201_5') Or  IsNamedPolygon('Q201_5') Or  IsNamedPolygon('SGND') Or  IsNamedPolygon('SGND') Or  IsNamedPolygon('Vout') Or  IsNamedPolygon('Vout') Or  IsNamedPolygon('IN+') Or  IsNamedPolygon('GND') Or  IsNamedPolygon('IN+') Or  IsNamedPolygon('GND')] p2: connectstyle=Direct reliefconductorwidth=0.254 reliefentries=4 polygonreliefangle="90 Angle" airgapwidth=0.254
PolygonConnect PolygonConnect_14 [All vs IsNamedPolygon('C106_2') Or  IsNamedPolygon('C107_2') Or  IsNamedPolygon('C107_2') Or  IsNamedPolygon('C107_2') Or  IsNamedPolygon('C102_1') Or  IsNamedPolygon('Q203_5') Or  IsNamedPolygon('Vout') Or  IsNamedPolygon('Q203_5') Or  IsNamedPolygon('Q203_5') Or  IsNamedPolygon('Q201_5') Or  IsNamedPolygon('C108_2') Or  IsNamedPolygon('Q203_5') Or  IsNamedPolygon('HS') Or  IsNamedPolygon('HV') Or  IsNamedPolygon('C108_2') Or  IsNamedPolygon('Q201_5') Or  IsNamedPolygon('C109_2') Or  IsNamedPolygon('Q201_5') Or  IsNamedPolygon('Q201_5') Or  IsNamedPolygon('C113_2')] p3: connectstyle=Direct reliefconductorwidth=0.254 reliefentries=4 polygonreliefangle="90 Angle" airgapwidth=0.254
PolygonConnect PolygonConnect_13 [All vs IsNamedPolygon('C102_1') Or  IsNamedPolygon('HV') Or  IsNamedPolygon('C107_2') Or  IsNamedPolygon('C109_2') Or  IsNamedPolygon('C107_2') Or  IsNamedPolygon('C108_2') Or  IsNamedPolygon('C106_2') Or  IsNamedPolygon('C108_2') Or  IsNamedPolygon('C113_2') Or  IsNamedPolygon('C107_2')] p4: connectstyle=Direct reliefconductorwidth=0.254 reliefentries=4 polygonreliefangle="90 Angle" airgapwidth=0.254
PolygonConnect PolygonConnect_12 [All vs IsNamedPolygon('C107_2') Or  IsNamedPolygon('C113_2') Or  IsNamedPolygon('C106_2') Or  IsNamedPolygon('C107_2') Or  IsNamedPolygon('C107_2') Or  IsNamedPolygon('C102_1')] p5: connectstyle=Direct reliefconductorwidth=0.254 reliefentries=4 polygonreliefangle="90 Angle" airgapwidth=0.254
PolygonConnect PolygonConnect_11 [All vs IsNamedPolygon('C106_2') Or  IsNamedPolygon('C102_1') Or  IsNamedPolygon('C107_2') Or  IsNamedPolygon('C107_2') Or  IsNamedPolygon('C107_2')] p6: connectstyle=Direct reliefconductorwidth=0.254 reliefentries=4 polygonreliefangle="90 Angle" airgapwidth=0.254
PolygonConnect PolygonConnect_10 [All vs IsNamedPolygon('C106_2')] p7: connectstyle=Direct reliefconductorwidth=0.254 reliefentries=4 polygonreliefangle="90 Angle" airgapwidth=0.254
PolygonConnect PolygonConnect_9 [All vs IsNamedPolygon('C11_1') Or  IsNamedPolygon('Vin') Or  IsNamedPolygon('Vin') Or  IsNamedPolygon('5V') Or  IsNamedPolygon('D6_2') Or  IsNamedPolygon('Q3_3') Or  IsNamedPolygon('GND2') Or  IsNamedPolygon('GND2') Or  IsNamedPolygon('GND') Or  IsNamedPolygon('Q3_4') Or  IsNamedPolygon('12V5') Or  IsNamedPolygon('GND') Or  IsNamedPolygon('12V5') Or  IsNamedPolygon('D3_1')] p8: connectstyle=Direct reliefconductorwidth=0.254 reliefentries=4 polygonreliefangle="90 Angle" airgapwidth=0.254
PolygonConnect PolygonConnect_8 [All vs IsNamedPolygon('C11_1') Or  IsNamedPolygon('Vin') Or  IsNamedPolygon('12V5') Or  IsNamedPolygon('Q3_3') Or  IsNamedPolygon('GND2') Or  IsNamedPolygon('GND2') Or  IsNamedPolygon('5V') Or  IsNamedPolygon('Q3_4') Or  IsNamedPolygon('12V5')] p9: connectstyle=Direct reliefconductorwidth=0.254 reliefentries=4 polygonreliefangle="90 Angle" airgapwidth=0.254
PolygonConnect PolygonConnect_7 [All vs IsNamedPolygon('GND2') Or  IsNamedPolygon('GND2') Or  IsNamedPolygon('5V') Or  IsNamedPolygon('12V5') Or  IsNamedPolygon('12V5') Or  IsNamedPolygon('C11_1')] p10: connectstyle=Direct reliefconductorwidth=0.254 reliefentries=4 polygonreliefangle="90 Angle" airgapwidth=0.254
PolygonConnect PolygonConnect_6 [All vs IsNamedPolygon('GND2') Or  IsNamedPolygon('SGND') Or  IsNamedPolygon('GND1') Or  IsNamedPolygon('C901_1') Or  IsNamedPolygon('SGND') Or  IsNamedPolygon('GND2') Or  IsNamedPolygon('GND1')] p11: connectstyle=Direct reliefconductorwidth=0.254 reliefentries=4 polygonreliefangle="90 Angle" airgapwidth=0.254
PolygonConnect PolygonConnect_5 [All vs IsNamedPolygon('GND1') Or  IsNamedPolygon('GND1')] p12: connectstyle=Direct reliefconductorwidth=0.254 reliefentries=4 polygonreliefangle="90 Angle" airgapwidth=0.254
PolygonConnect PolygonConnect_4 [All vs IsNamedPolygon('C21_1') Or  IsNamedPolygon('C5_1') Or  IsNamedPolygon('C12_2') Or  IsNamedPolygon('C2_2') Or  IsNamedPolygon('C13_1') Or  IsNamedPolygon('C28_1') Or  IsNamedPolygon('C6_1') Or  IsNamedPolygon('GND') Or  IsNamedPolygon('GND2') Or  IsNamedPolygon('C14_1') Or  IsNamedPolygon('C13_1') Or  IsNamedPolygon('Q1_3') Or  IsNamedPolygon('C14_1') Or  IsNamedPolygon('C5_1') Or  IsNamedPolygon('GND2') Or  IsNamedPolygon('C28_1') Or  IsNamedPolygon('D5_2') Or  IsNamedPolygon('D6_2') Or  IsNamedPolygon('D2_1') Or  IsNamedPolygon('C12_2') Or  IsNamedPolygon('D2_1') Or  IsNamedPolygon('C4_1') Or  IsNamedPolygon('C4_1') Or  IsNamedPolygon('C2_2') Or  IsNamedPolygon('GND') Or  IsNamedPolygon('C33_1') Or  IsNamedPolygon('C9_1')] p13: connectstyle=Direct reliefconductorwidth=0.254 reliefentries=4 polygonreliefangle="90 Angle" airgapwidth=0.254
PolygonConnect PolygonConnect_3 [All vs IsNamedPolygon('C28_1') Or  IsNamedPolygon('C12_2') Or  IsNamedPolygon('C28_1') Or  IsNamedPolygon('C9_1') Or  IsNamedPolygon('D5_2') Or  IsNamedPolygon('C12_2') Or  IsNamedPolygon('C2_2') Or  IsNamedPolygon('C14_1') Or  IsNamedPolygon('C4_1') Or  IsNamedPolygon('C14_1') Or  IsNamedPolygon('D6_2') Or  IsNamedPolygon('GND2') Or  IsNamedPolygon('Q1_3') Or  IsNamedPolygon('C5_1') Or  IsNamedPolygon('D2_1') Or  IsNamedPolygon('C4_1') Or  IsNamedPolygon('C13_1') Or  IsNamedPolygon('C5_1') Or  IsNamedPolygon('C13_1') Or  IsNamedPolygon('C33_1') Or  IsNamedPolygon('D2_1') Or  IsNamedPolygon('GND') Or  IsNamedPolygon('GND') Or  IsNamedPolygon('GND2') Or  IsNamedPolygon('C2_2') Or  IsNamedPolygon('C6_1') Or  IsNamedPolygon('C21_1')] p14: connectstyle=Direct reliefconductorwidth=0.254 reliefentries=4 polygonreliefangle="90 Angle" airgapwidth=0.254
PolygonConnect PolygonConnect_2 [All vs IsNamedPolygon('C21_1') Or  IsNamedPolygon('C4_1') Or  IsNamedPolygon('D5_2') Or  IsNamedPolygon('C5_1') Or  IsNamedPolygon('C14_1') Or  IsNamedPolygon('C13_1') Or  IsNamedPolygon('C4_1') Or  IsNamedPolygon('C33_1') Or  IsNamedPolygon('C12_2') Or  IsNamedPolygon('D2_1') Or  IsNamedPolygon('C2_2') Or  IsNamedPolygon('C28_1') Or  IsNamedPolygon('C12_2') Or  IsNamedPolygon('D2_1') Or  IsNamedPolygon('C5_1') Or  IsNamedPolygon('Q1_3') Or  IsNamedPolygon('GND') Or  IsNamedPolygon('D6_2') Or  IsNamedPolygon('C6_1') Or  IsNamedPolygon('C2_2') Or  IsNamedPolygon('C14_1') Or  IsNamedPolygon('C28_1') Or  IsNamedPolygon('C13_1') Or  IsNamedPolygon('C9_1') Or  IsNamedPolygon('GND')] p15: connectstyle=Direct reliefconductorwidth=0.254 reliefentries=4 polygonreliefangle="90 Angle" airgapwidth=0.254
PolygonConnect PolygonConnect_1 [All vs IsNamedPolygon('C28_1') Or  IsNamedPolygon('D5_2') Or  IsNamedPolygon('C5_1') Or  IsNamedPolygon('C5_1') Or  IsNamedPolygon('D2_1') Or  IsNamedPolygon('C21_1') Or  IsNamedPolygon('C9_1') Or  IsNamedPolygon('C4_1') Or  IsNamedPolygon('C14_1') Or  IsNamedPolygon('C28_1') Or  IsNamedPolygon('C6_1') Or  IsNamedPolygon('C12_2') Or  IsNamedPolygon('C33_1') Or  IsNamedPolygon('C4_1') Or  IsNamedPolygon('C13_1') Or  IsNamedPolygon('C12_2') Or  IsNamedPolygon('D6_2') Or  IsNamedPolygon('C2_2') Or  IsNamedPolygon('C14_1') Or  IsNamedPolygon('D2_1') Or  IsNamedPolygon('C2_2') Or  IsNamedPolygon('C13_1')] p16: connectstyle=Direct reliefconductorwidth=0.254 reliefentries=4 polygonreliefangle="90 Angle" airgapwidth=0.254
PolygonConnect [All] p17: connectstyle=Direct reliefconductorwidth=0.254 reliefentries=4 polygonreliefangle="90 Angle" airgapwidth=0.254
RoutingLayers [All] p1: top layer_v5=TRUE mid layer 1_v5=TRUE mid layer 2_v5=TRUE mid layer 3_v5=TRUE mid layer 4_v5=TRUE mid layer 5_v5=FALSE mid layer 6_v5=FALSE bottom layer_v5=TRUE
RoutingVias ThermalPadVias [IsVia and not InNet('SGND')and not InNet('Vout')] p1: holewidth=0.2 width=0.5 viastyle="Through Hole" minholewidth=0.2 minwidth=0.5 maxholewidth=0.432 maxwidth=0.889
RoutingVias [IsVia and not InNet('SGND')and not InNet('Vout')] p2: holewidth=0.406 width=0.864 viastyle="Through Hole" minholewidth=0.2 minwidth=0.508 maxholewidth=1.016 maxwidth=1.651
SilkToBoardRegionClearance [Not ((IsComment or IsDesignator) And (Hide <> 'False')) and not InRegion(1000,500,4000,800)] p1:
SilkToSilkClearance SilkToSilkClearance_Pb-FreeLogo [(HasFootprint('Pb-Free_Overlay_Medium') OR HasFootprint('Pb-Free_Overlay_Small')) vs (HasFootprint('Pb-Free_Overlay_Medium') OR HasFootprint('Pb-Free_Overlay_Small'))] p1: silktosilkclearance=0
SilkToSilkClearance [All] p2: silktosilkclearance=0.076
SilkToSolderMaskClearance "Silk to Solder Mask Opening" [All] p1: minsilkscreentomaskgap=0.025 clearancetoexposedcopper=FALSE
SolderMaskExpansion [All] p1: expansion=0.05
UnpouredPolygon [All] p1: allowunpoured=TRUE allowshelved=TRUE
Width [All] p1: maxlimit=2.54 minlimit=0.152 preferedwidth=0.254 checkconnectedcopper=TRUE
12 further rules are at their usual default settings.

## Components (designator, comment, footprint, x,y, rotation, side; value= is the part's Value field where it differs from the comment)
C1 "C1608X5R1H104K080AA" 0603L 11.485,27.231 r0 bottom value=0.1uF
C2 "C0603C101J5GACTU" 0603L 14.249,34.29 r180 bottom value=100pF
C3 "C0603C101J5GACTU" 0603L 10.744,29.146 r270 bottom value=100pF
C4 "GRM188R71E103KA01D" 0603L 3.628,25.565 r0 bottom value=0.01uF
D1 "MMSZ5245BS-7-F" SOD-323 17.551,33.845 r180 bottom value=15V
D2 "BAS316,115" SOD-323 21.895,33.845 r0 bottom value=100V
Q1 "CSD16570Q5B" DNK0008A#1 23.406,29.603 r0 top value=25V
Q2 "CSD16570Q5B" DNK0008A#1 23.409,23.853 r0 top value=25V
Q3 "CSD16570Q5B" DNK0008A#1 23.391,18.023 r0 top value=25V
Q4 "CSD16570Q5B" DNK0008A#1 23.409,12.353 r0 top value=25V
Q5 "CSD16570Q5B" DNK0008A#2 23.304,29.544 r0 bottom value=25V
Q6 "CSD16570Q5B" DNK0008A#2 23.307,23.794 r0 bottom value=25V
Q7 "CSD16570Q5B" DNK0008A#2 23.289,17.964 r0 bottom value=25V
Q8 "CSD16570Q5B" DNK0008A#2 23.307,12.294 r0 bottom value=25V
Q9 "CSD16570Q5B" DNK0008A#1 23.439,6.704 r0 top value=25V
Q10 "CSD16570Q5B" DNK0008A#2 23.337,6.646 r0 bottom value=25V
R1 "CRCW04025K11FKED" 0402L 14.376,33.007 r0 bottom value=5.11k
R2 "RC0402FR-0710KL" 0402L 5.443,34.15 r90 bottom value=10.0k
R3 "MCR01MZPF10R0" 0402L 3.628,24.244 r0 bottom value=10.0
R4 "RC0402FR-0710KL" 0402L 3.77,33.795 r180 bottom value=10.0k
R5 "RC0402FR-07100KL" 0402L 5.384,25.171 r270 bottom value=100k
R6 "RC0402FR-0710KL" 0402L 2.048,30.408 r270 bottom value=10.0k
R7 "CRCW0402549RFKED" 0402L 3.77,32.495 r0 bottom value=549
R8 "WSLP20101L000FEA" WSLP2010-001 15.31,5.388 r0 top value=0.001
R9 "WSLP20101L000FEA" WSLP2010-001 15.31,8.577 r0 top value=0.001
R10 "WSLP20101L000FEA" WSLP2010-001 15.31,11.687 r0 top value=0.001
R11 "WSLP20101L000FEA" WSLP2010-001 15.31,14.76 r0 top value=0.001
R12 "WSLP20101L000FEA" WSLP2010-001 15.31,17.834 r0 top value=0.001
R13 "WSLP20101L000FEA" WSLP2010-001 15.31,20.909 r0 top value=0.001
R14 "WSLP20101L000FEA" WSLP2010-001 15.31,24.033 r0 top value=0.001
R15 "WSLP20101L000FEA" WSLP2010-001 15.31,27.081 r0 top value=0.001
R16 "WSLP20101L000FEA" WSLP2010-001 15.31,30.154 r0 top value=0.001
R17 "WSLP20101L000FEA" WSLP2010-001 15.31,33.273 r0 top value=0.001
U1 "TPS2411PWR" PW0014A_L 5.97,29.108 r0 bottom

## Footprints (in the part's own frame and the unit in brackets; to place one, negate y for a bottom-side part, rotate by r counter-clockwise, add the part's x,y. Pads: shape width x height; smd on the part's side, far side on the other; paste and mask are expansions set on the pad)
0402L [mm] "0402 from SM-752 data"
  rect 0.6x0.5 smd: 1(-0.5,0) 2(0.5,0)
  body extent -0.55,-0.3 0.55,0.3, height 0.6
0603L [mm] "0603 from SM-752 data"
  rect 0.8x0.85 smd: 1(-0.7,0) 2(0.7,0)
  silkscreen extent -0.07,-0.33 0.07,0.33, body extent -0.87,-0.47 0.87,0.47, height 1
DNK0008A#1 [mm] "SON, 8-Leads, Body 5x6mm"
  rrect39% 0.86x0.51 smd paste-0.05 mask-0.05: 1(-2.82,1.905) 2(-2.82,0.635) 3(-2.82,-0.635) 4(-2.82,-1.905) 5(2.82,-1.905) 6(2.82,-0.635) 7(2.82,0.635) 8(2.82,1.905)
  rrect40% 0.25x0.555 on Top Solder: 9(-0.83,-2.372) 9(-0.83,2.372)
  rrect40% 0.25x0.555 on Top Paste: 9(-0.83,-2.372) 9(-0.83,2.372)
  rrect11% 0.95x1.13 on Top Paste: 9(-0.535,-1.33) 9(-0.535,0) 9(-0.535,1.33) 9(0.615,-1.33) 9(0.615,0) 9(0.615,1.33) 9(1.765,-1.33) 9(1.765,0) 9(1.765,1.33)
  rrect3% 3.58x4 on Top Solder: 9(0.75,0)
  rrect5% 4.34x5.4 smd paste-3 mask-3: 9(1.08,0)
  body extent -3.05,-2.55 3.05,2.55, height 1.06
DNK0008A#2 [mm] "SON, 8-Leads, Body 5x6mm"
  rrect39% 0.86x0.51 smd paste-0.05 mask-0.05: 1(-2.82,1.905) 2(-2.82,0.635) 3(-2.82,-0.635) 4(-2.82,-1.905) 5(2.82,-1.905) 6(2.82,-0.635) 7(2.82,0.635) 8(2.82,1.905)
  rrect40% 0.25x0.555 on Bottom Solder: 9(-0.83,-2.372) 9(-0.83,2.372)
  rrect40% 0.25x0.555 on Bottom Paste: 9(-0.83,-2.372) 9(-0.83,2.372)
  rrect11% 0.95x1.13 on Bottom Paste: 9(-0.535,-1.33) 9(-0.535,0) 9(-0.535,1.33) 9(0.615,-1.33) 9(0.615,0) 9(0.615,1.33) 9(1.765,-1.33) 9(1.765,0) 9(1.765,1.33)
  rrect3% 3.58x4 on Bottom Solder: 9(0.75,0)
  rrect5% 4.34x5.4 smd paste-3 mask-3: 9(1.08,0)
  body extent -3.05,-2.55 3.05,2.55, height 1.06
PW0014A_L [mm] "TSOP, 14-Leads, Body 5x4.4mm, Pitch 0.65mm, IPC High Density"
  oval 1.2x0.4 smd: 1(-2.85,1.95) 2(-2.85,1.3) 3(-2.85,0.65) 4(-2.85,0) 5(-2.85,-0.65) 6(-2.85,-1.3) 7(-2.85,-1.95) 8(2.85,-1.95) 9(2.85,-1.3) 10(2.85,-0.65) 11(2.85,0) 12(2.85,0.65) 13(2.85,1.3) 14(2.85,1.95)
  silkscreen extent -3.2,-2.55 1.85,2.55, body extent -3.21,-2.5 3.21,2.5, height 1
SOD-323 [mm] "NXP recommended land pattern"
  rect 0.6x0.6 smd paste-0.05: 1(-1.1,0) 2(1.1,0)
  silkscreen extent -2.06,-0.86 1.53,0.86, body extent -1.3,-0.67 1.3,0.68, height 1.1
WSLP2010-001 [mm] "Vishay"
  rrect4% 2.36x3.05 smd: 1(-1.88,0) 2(1.88,0)
  silkscreen extent -0.4,-1.5 0.4,1.5, body extent -2.54,-1.27 2.54,1.27, height 0.66

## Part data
C1: library part CMP-0007010-5, "CAP, CERM, 0.1 uF, 50 V, +/- 10%, X5R, 0603", Cap_Case=0603, Manufacturer=TDK, Supplier Part Number 1=445-7456-1-ND, TempCo=X5R, Tolerance_%=10%, Value1="0.0296 ohm", Value2=50V, ValueDisplayed=0.1uF
C2 C3: library part CMP-0006841-4, "CAP, CERM, 100 pF, 50 V, +/- 5%, C0G/NP0, 0603", Cap_Case=0603, Manufacturer=Kemet, Supplier Part Number 1=399-1061-1-ND, TempCo=C0G/NP0, Tolerance_%=5%, Value1=Unknown, Value2=50V, ValueDisplayed=100pF
C4: library part CMP-0007403-4, "CAP, CERM, 0.01 uF, 25 V, +/- 10%, X7R, 0603", Cap_Case=0603, Manufacturer=MuRata, Supplier Part Number 1=490-1520-1-ND, TempCo=X7R, Tolerance_%=10%, Value1=Unknown, Value2=25V, ValueDisplayed=0.01uF
D1: library part CMP-0005833-4, "Diode, Zener, 15 V, 200 mW, SOD-323", Manufacturer="Diodes Inc.", Power_W=200mW, Value1=0.2W
D2: library part CMP-0029006-2, "Diode, Ultrafast, 100 V, 0.25 A, SOD-323", Manufacturer=Nexperia, Value1=0.25A, Value2=1.4V
Q1 Q2 Q3 Q4 Q5 Q6 Q7 Q8 Q9 Q10: library part CMP-0000274-2, "MOSFET, N-CH, 25 V, 100 A, DNK0008A (VSON-CLIP-8)", Alternate Manufacturer=None, Manufacturer="Texas Instruments", Supplier Part Number 1=CSD16570Q5B-ND, Value1=0, Value2="192 nC"
R1: library part CMP-0026463-2, "RES, 5.11 k, 1%, 0.063 W, AEC-Q200 Grade 0, 0402", Manufacturer=Vishay-Dale, Power_W=63mW, Supplier Part Number 1=541-5.11KLCT-ND, TempCo="100 ppm/C", Tolerance_%=1%, Value2=0.063W, Value_Code=5k11, ValueDisplayed=5.11k
R2 R4 R6: library part CMP-0078669-1, "RES, 10.0 k, 1%, 0.063 W, 0402", Manufacturer="Yageo America", Power_W=63mW, Supplier Part Number 1=311-10.0KLRCT-ND, TempCo="100 ppm/C", Tolerance_%=1%, Value2=0.063W, Value_Code=10k0, ValueDisplayed=10.0k
R3: library part CMP-0026717-1, "RES, 10.0, 1%, 0.063 W, 0402", Manufacturer=Rohm, Power_W=63mW, Supplier Part Number 1=RHM10.0LCT-ND, TempCo="100 ppm/C", Tolerance_%=1%, Value2=0.063W, Value_Code=10R0, ValueDisplayed=10.0
R5: library part CMP-0026721-1, "RES, 100 k, 1%, 0.0625 W, 0402", Manufacturer="Yageo America", Power_W=62.5mW, Supplier Part Number 1=311-100KLRCT-ND, TempCo="100 ppm/C", Tolerance_%=1%, Value2=0.0625W, Value_Code=100k
R7: library part CMP-0026448-2, "RES, 549, 1%, 0.063 W, AEC-Q200 Grade 0, 0402", Manufacturer=Vishay-Dale, Power_W=63mW, Supplier Part Number 1=541-549LCT-ND, TempCo="100 ppm/C", Tolerance_%=1%, Value2=0.063W, Value_Code=549R, ValueDisplayed=549
R8 R9 R10 R11 R12 R13 R14 R15 R16 R17: library part CMP-0016564-3, "RES, 0.001, 1%, 2 W, 2010", Manufacturer=Vishay-Dale, Power_W=2W, Supplier Part Number 1=54X6168, TempCo="275 ppm/C", Tolerance_%=1%, Value_Code=1L000, ValueDisplayed=0.001
U1: library part CMP-0038282-1, "N+1 and OR-ing Power Rail Controller, 0.8 to 16.5 V, -40 to 85 degC, 14-pin TSSOP (PW), Green (RoHS & no Sb/Br)", Manufacturer="Texas Instruments", Under/Over Voltage Reporting=Yes

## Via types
v1: diameter 0.61, hole 0.203, Top Layer to Bottom Layer, 996 vias
v2: diameter 0.61, hole 0.203, Top Layer to Bottom Layer, tented both sides, 18 vias
v3: diameter 0.508, hole 0.254, Top Layer to Bottom Layer, 1 vias

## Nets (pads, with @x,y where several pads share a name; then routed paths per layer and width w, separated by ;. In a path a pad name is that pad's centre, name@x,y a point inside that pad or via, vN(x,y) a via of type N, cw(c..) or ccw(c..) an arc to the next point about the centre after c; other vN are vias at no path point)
12VA: C1.2 C3.1 D1.2 Q1.1 Q1.2 Q1.3 Q2.1 Q2.2 Q2.3 Q3.1 Q3.2 Q3.3 Q4.1 Q4.2 Q4.3 Q5.1 Q5.2 Q5.3 Q6.1 Q6.2 Q6.3 Q7.1 Q7.2 Q7.3 Q8.1 Q8.2 Q8.3 Q9.1 Q9.2 Q9.3 Q10.1 Q10.2 Q10.3 R2.2 R4.2 R8.2 R9.2 R10.2 R11.2 R12.2 R13.2 R14.2 R15.2 R16.2 R17.2 U1.11 | length 82.8
  Top Layer w0.305: 1.041,4.213 1.096,4.267 1.096,5.944 1.396,6.244 v2(1.396,7.705)
  Layer 2 w0.305: v2(4.445,34.683) 4.445,30.777 v2(5.813,29.409)
  Layer 3 w0.305: v2(1.396,7.705) 1.396,9.494 2.159,10.258 2.159,26.985 3.826,28.651 14.619,28.651 15.491,27.779 15.491,20.472 15.696,20.267 ; v2@5.813,29.492 v2(5.813,29.409) 6.114,29.108 14.834,29.108 15.995,27.947 15.995,20.566 15.696,20.267 ; v2(15.696,19.05) 15.696,20.267
  Bottom Layer w0.305: R4.2@3.27,33.795 3.27,34.145 3.75,34.625 4.387,34.625 v2(4.445,34.683) 4.462,34.667 5.426,34.667 R2.2@5.443,34.65 ; v2(5.813,29.409) 5.843,29.409 6.144,29.108 U1.11@8.82,29.108 9.72,29.108 10.21,29.599 10.497,29.599 C3.1@10.744,29.846 11.632,29.846 12.185,29.293 C1.2@12.185,27.523 ; C1.2@12.185,27.231 12.195,27.241 C1.2@12.195,27.523
  other v1: 16.48,3.658 17.153,3.658 17.829,3.658 18.5,3.658 19.075,3.962 19.075,5.283 19.406,5.944 19.075,6.604 19.406,7.264 19.075,7.925 19.406,8.585 19.075,9.246 19.406,9.906 19.075,10.566 19.406,11.227 19.075,11.887 19.406,12.548 19.075,13.208 19.406,13.868 19.075,14.529 19.406,15.189 19.075,15.85 19.083,16.54 19.075,17.17 19.406,19.152 19.021,19.812 19.406,20.472 19.075,21.133 19.075,22.454 19.406,23.114 19.075,23.774 19.406,24.435 19.075,25.095 19.406,25.756 19.075,26.416 19.406,27.262 19.05,28.007 19.406,28.782 19.05,29.625
12VB: C2.1 Q1.5 Q1.6 Q1.7 Q1.8 Q1.9@24.486,29.603 Q2.5 Q2.6 Q2.7 Q2.8 Q2.9@24.489,23.853 Q3.5 Q3.6 Q3.7 Q3.8 Q3.9@24.471,18.023 Q4.5 Q4.6 Q4.7 Q4.8 Q4.9@24.489,12.353 Q5.5 Q5.6 Q5.7 Q5.8 Q5.9@24.384,29.544 Q6.5 Q6.6 Q6.7 Q6.8 Q6.9@24.387,23.794 Q7.5 Q7.6 Q7.7 Q7.8 Q7.9@24.369,17.964 Q8.5 Q8.6 Q8.7 Q8.8 Q8.9@24.387,12.294 Q9.5 Q9.6 Q9.7 Q9.8 Q9.9@24.519,6.704 Q10.5 Q10.6 Q10.7 Q10.8 Q10.9@24.417,6.646 R1.2 | length 25.4
  Top Layer w0.254: v2(21.565,18.034) 21.576,18.023 22.053,18.023
  Layer 3 w0.508: v3@14.986,32.181 14.986,29.814 16.601,28.199 16.601,18.961 17.528,18.034 v2(21.565,18.034)
  Bottom Layer w0.254: Q7.9@22.606,18.034 24.3,18.034 Q7.9@24.369,17.964
  Bottom Layer w0.305: R1.2@14.876,33.007 R1.2@14.913,33.044 ; Q5.9@24.384,29.544 Q5.9@24.384,30.074
  Bottom Layer w0.508: C2.1@14.986,34.253 C2.1@14.949,34.29 14.949,32.934 15.24,32.643 v3(15.24,32.181) ; v2(21.565,18.034) Q7.9@22.606,18.034
  other v1: 21.9,0.66 22.6,0.66 23.3,0.66 24,0.66 24.689,0.66 25.349,0.66 26.01,0.66 26.67,0.66 27.33,0.66 27.991,0.66 28.651,0.66 29.312,0.66 29.972,0.66 30.632,0.66 31.293,0.66 31.953,0.66 32.614,0.66 33.274,0.66 22.23,1.321 22.93,1.321 23.63,1.321 24.33,1.321 25.019,1.321 25.679,1.321 26.34,1.321 27,1.321 27.661,1.321 28.321,1.321 28.981,1.321 29.642,1.321 30.302,1.321 30.963,1.321 31.623,1.321 32.283,1.321 32.944,1.321 33.604,1.321 21.9,1.981 22.6,1.981 23.3,1.981 24,1.981 24.689,1.981 25.349,1.981 26.01,1.981 26.67,1.981 27.33,1.981 27.991,1.981 28.651,1.981 29.312,1.981 29.972,1.981 30.632,1.981 31.293,1.981 31.953,1.981 32.614,1.981 33.274,1.981 22.23,2.642 22.93,2.642 23.63,2.642 24.33,2.642 25.019,2.642 25.679,2.642 26.34,2.642 27,2.642 27.661,2.642 28.321,2.642 28.981,2.642 29.642,2.642 30.302,2.642 30.963,2.642 31.623,2.642 32.283,2.642 32.944,2.642 33.604,2.642 21.9,3.302 22.6,3.302 23.3,3.302 24,3.302 24.689,3.302 25.349,3.302 26.01,3.302 26.67,3.302 27.33,3.302 27.991,3.302 28.651,3.302 29.312,3.302 29.972,3.302 30.632,3.302 31.293,3.302 31.953,3.302 32.614,3.302 33.274,3.302 27.661,3.962 28.321,3.962 28.981,3.962 29.642,3.962 30.302,3.962 30.963,3.962 31.623,3.962 32.283,3.962 32.944,3.962 33.604,3.962 27.33,4.623 27.991,4.623 28.651,4.623 29.312,4.623 29.972,4.623 30.632,4.623 31.293,4.623 31.953,4.623 32.614,4.623 33.274,4.623 27.661,5.283 28.321,5.283 28.981,5.283 29.642,5.283 30.302,5.283 30.963,5.283 31.623,5.283 32.283,5.283 32.944,5.283 33.604,5.283 27.33,5.944 27.991,5.944 28.651,5.944 29.312,5.944 29.972,5.944 30.632,5.944 31.293,5.944 31.953,5.944 32.614,5.944 33.274,5.944 27.661,6.604 28.321,6.604 28.981,6.604 29.642,6.604 30.302,6.604 30.963,6.604 31.623,6.604 32.283,6.604 32.944,6.604 33.604,6.604 27.33,7.264 27.991,7.264 28.651,7.264 29.312,7.264 29.972,7.264 30.632,7.264 31.293,7.264 31.953,7.264 32.614,7.264 33.274,7.264 27.661,7.925 28.321,7.925 28.981,7.925 29.642,7.925 30.302,7.925 30.963,7.925 31.623,7.925 32.283,7.925 32.944,7.925 33.604,7.925 27.33,8.585 27.991,8.585 28.651,8.585 29.312,8.585 29.972,8.585 30.632,8.585 31.293,8.585 31.953,8.585 32.614,8.585 33.274,8.585 27.661,9.246 28.321,9.246 28.981,9.246 29.642,9.246 30.302,9.246 30.963,9.246 31.623,9.246 32.283,9.246 32.944,9.246 33.604,9.246 27.33,9.906 27.991,9.906 28.651,9.906 29.312,9.906 29.972,9.906 30.632,9.906 31.293,9.906 31.953,9.906 32.614,9.906 33.274,9.906 27.661,10.566 28.321,10.566 28.981,10.566 29.642,10.566 30.302,10.566 30.963,10.566 31.623,10.566 32.283,10.566 32.944,10.566 33.604,10.566 27.33,11.227 27.991,11.227 28.651,11.227 29.312,11.227 29.972,11.227 30.632,11.227 31.293,11.227 31.953,11.227 32.614,11.227 33.274,11.227 27.661,11.887 28.321,11.887 28.981,11.887 29.642,11.887 30.302,11.887 30.963,11.887 31.623,11.887 32.283,11.887 32.944,11.887 33.604,11.887 27.33,12.548 27.991,12.548 28.651,12.548 29.312,12.548 29.972,12.548 30.632,12.548 31.293,12.548 31.953,12.548 32.614,12.548 33.274,12.548 27.661,13.208 28.321,13.208 28.981,13.208 29.642,13.208 30.302,13.208 30.963,13.208 31.623,13.208 32.283,13.208 32.944,13.208 33.604,13.208 27.33,13.868 27.991,13.868 28.651,13.868 29.312,13.868 29.972,13.868 30.632,13.868 31.293,13.868 31.953,13.868 32.614,13.868 33.274,13.868 27.661,14.529 28.321,14.529 28.981,14.529 29.642,14.529 30.302,14.529 30.963,14.529 31.623,14.529 32.283,14.529 32.944,14.529 33.604,14.529 27.33,15.189 27.991,15.189 28.651,15.189 29.312,15.189 29.972,15.189 30.632,15.189 31.293,15.189 31.953,15.189 32.614,15.189 33.274,15.189 27.661,15.85 28.321,15.85 28.981,15.85 29.642,15.85 30.302,15.85 30.963,15.85 31.623,15.85 32.283,15.85 32.944,15.85 33.604,15.85 27.33,16.51 27.991,16.51 28.651,16.51 29.312,16.51 29.972,16.51 30.632,16.51 31.293,16.51 31.953,16.51 32.614,16.51 33.274,16.51 27.661,17.17 28.321,17.17 28.981,17.17 29.642,17.17 30.302,17.17 30.963,17.17 31.623,17.17 32.283,17.17 32.944,17.17 33.604,17.17 27.33,17.831 27.991,17.831 28.651,17.831 29.312,17.831 29.972,17.831 30.632,17.831 31.293,17.831 31.953,17.831 32.614,17.831 33.274,17.831 27.661,18.491 28.321,18.491 28.981,18.491 29.642,18.491 30.302,18.491 30.963,18.491 31.623,18.491 32.283,18.491 32.944,18.491 33.604,18.491 27.33,19.152 27.991,19.152 28.651,19.152 29.312,19.152 29.972,19.152 30.632,19.152 31.293,19.152 31.953,19.152 32.614,19.152 33.274,19.152 27.661,19.812 28.321,19.812 28.981,19.812 29.642,19.812 30.302,19.812 30.963,19.812 31.623,19.812 32.283,19.812 32.944,19.812 33.604,19.812 27.33,20.472 27.991,20.472 28.651,20.472 29.312,20.472 29.972,20.472 30.632,20.472 31.293,20.472 31.953,20.472 32.614,20.472 33.274,20.472 27.661,21.133 28.321,21.133 28.981,21.133 29.642,21.133 30.302,21.133 30.963,21.133 31.623,21.133 32.283,21.133 32.944,21.133 33.604,21.133 27.33,21.793 27.991,21.793 28.651,21.793 29.312,21.793 29.972,21.793 30.632,21.793 31.293,21.793 31.953,21.793 32.614,21.793 33.274,21.793 27.661,22.454 28.321,22.454 28.981,22.454 29.642,22.454 30.302,22.454 30.963,22.454 31.623,22.454 32.283,22.454 32.944,22.454 33.604,22.454 27.33,23.114 27.991,23.114 28.651,23.114 29.312,23.114 29.972,23.114 30.632,23.114 31.293,23.114 31.953,23.114 32.614,23.114 33.274,23.114 27.661,23.774 28.321,23.774 28.981,23.774 29.642,23.774 30.302,23.774 30.963,23.774 31.623,23.774 32.283,23.774 32.944,23.774 33.604,23.774 27.33,24.435 27.991,24.435 28.651,24.435 29.312,24.435 29.972,24.435 30.632,24.435 31.293,24.435 31.953,24.435 32.614,24.435 33.274,24.435 27.661,25.095 28.321,25.095 28.981,25.095 29.642,25.095 30.302,25.095 30.963,25.095 31.623,25.095 32.283,25.095 32.944,25.095 33.604,25.095 27.33,25.756 27.991,25.756 28.651,25.756 29.312,25.756 29.972,25.756 30.632,25.756 31.293,25.756 31.953,25.756 32.614,25.756 33.274,25.756 27.661,26.416 28.321,26.416 28.981,26.416 29.642,26.416 30.302,26.416 30.963,26.416 31.623,26.416 32.283,26.416 32.944,26.416 33.604,26.416 27.33,27.076 27.991,27.076 28.651,27.076 29.312,27.076 29.972,27.076 30.632,27.076 31.293,27.076 31.953,27.076 32.614,27.076 33.274,27.076 27.661,27.737 28.321,27.737 28.981,27.737 29.642,27.737 30.302,27.737 30.963,27.737 31.623,27.737 32.283,27.737 32.944,27.737 33.604,27.737 27.33,28.397 27.991,28.397 28.651,28.397 29.312,28.397 29.972,28.397 30.632,28.397 31.293,28.397 31.953,28.397 32.614,28.397 33.274,28.397 27.661,29.058 28.321,29.058 28.981,29.058 29.642,29.058 30.302,29.058 30.963,29.058 31.623,29.058 32.283,29.058 32.944,29.058 33.604,29.058 27.33,29.718 27.991,29.718 28.651,29.718 29.312,29.718 29.972,29.718 30.632,29.718 31.293,29.718 31.953,29.718 32.614,29.718 33.274,29.718 27.661,30.378 28.321,30.378 28.981,30.378 29.642,30.378 30.302,30.378 30.963,30.378 31.623,30.378 32.283,30.378 32.944,30.378 33.604,30.378 27.33,31.039 27.991,31.039 28.651,31.039 29.312,31.039 29.972,31.039 30.632,31.039 31.293,31.039 31.953,31.039 32.614,31.039 33.274,31.039 27.661,31.699 28.321,31.699 28.981,31.699 29.642,31.699 30.302,31.699 30.963,31.699 31.623,31.699 32.283,31.699 32.944,31.699 33.604,31.699 27.33,32.36 27.991,32.36 28.651,32.36 29.312,32.36 29.972,32.36 30.632,32.36 31.293,32.36 31.953,32.36 32.614,32.36 33.274,32.36 24.359,33.02 25.019,33.02 25.679,33.02 26.34,33.02 27,33.02 27.661,33.02 28.321,33.02 28.981,33.02 29.642,33.02 30.302,33.02 30.963,33.02 31.623,33.02 32.283,33.02 32.944,33.02 33.604,33.02 24.689,33.68 25.349,33.68 26.01,33.68 26.67,33.68 27.33,33.68 27.991,33.68 28.651,33.68 29.312,33.68 29.972,33.68 30.632,33.68 31.293,33.68 31.953,33.68 32.614,33.68 24.359,34.341 25.019,34.341 25.679,34.341 26.34,34.341 27,34.341 27.661,34.341 28.321,34.341 28.981,34.341 29.642,34.341 30.302,34.341 30.963,34.341 31.623,34.341 32.283,34.341
12VS: R3.2 | length 20.6
  Bottom Layer w0.508: 2.664,4.372 2.59,4.446 2.59,7.957 4.128,9.495 R3.2@4.128,24.244 4.134,24.244 R3.2@4.138,24.24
